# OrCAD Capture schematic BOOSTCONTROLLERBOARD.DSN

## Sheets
1 1 Microcontroller: size C; title: Boost Controller Board - Microcontroller; note: 10021168
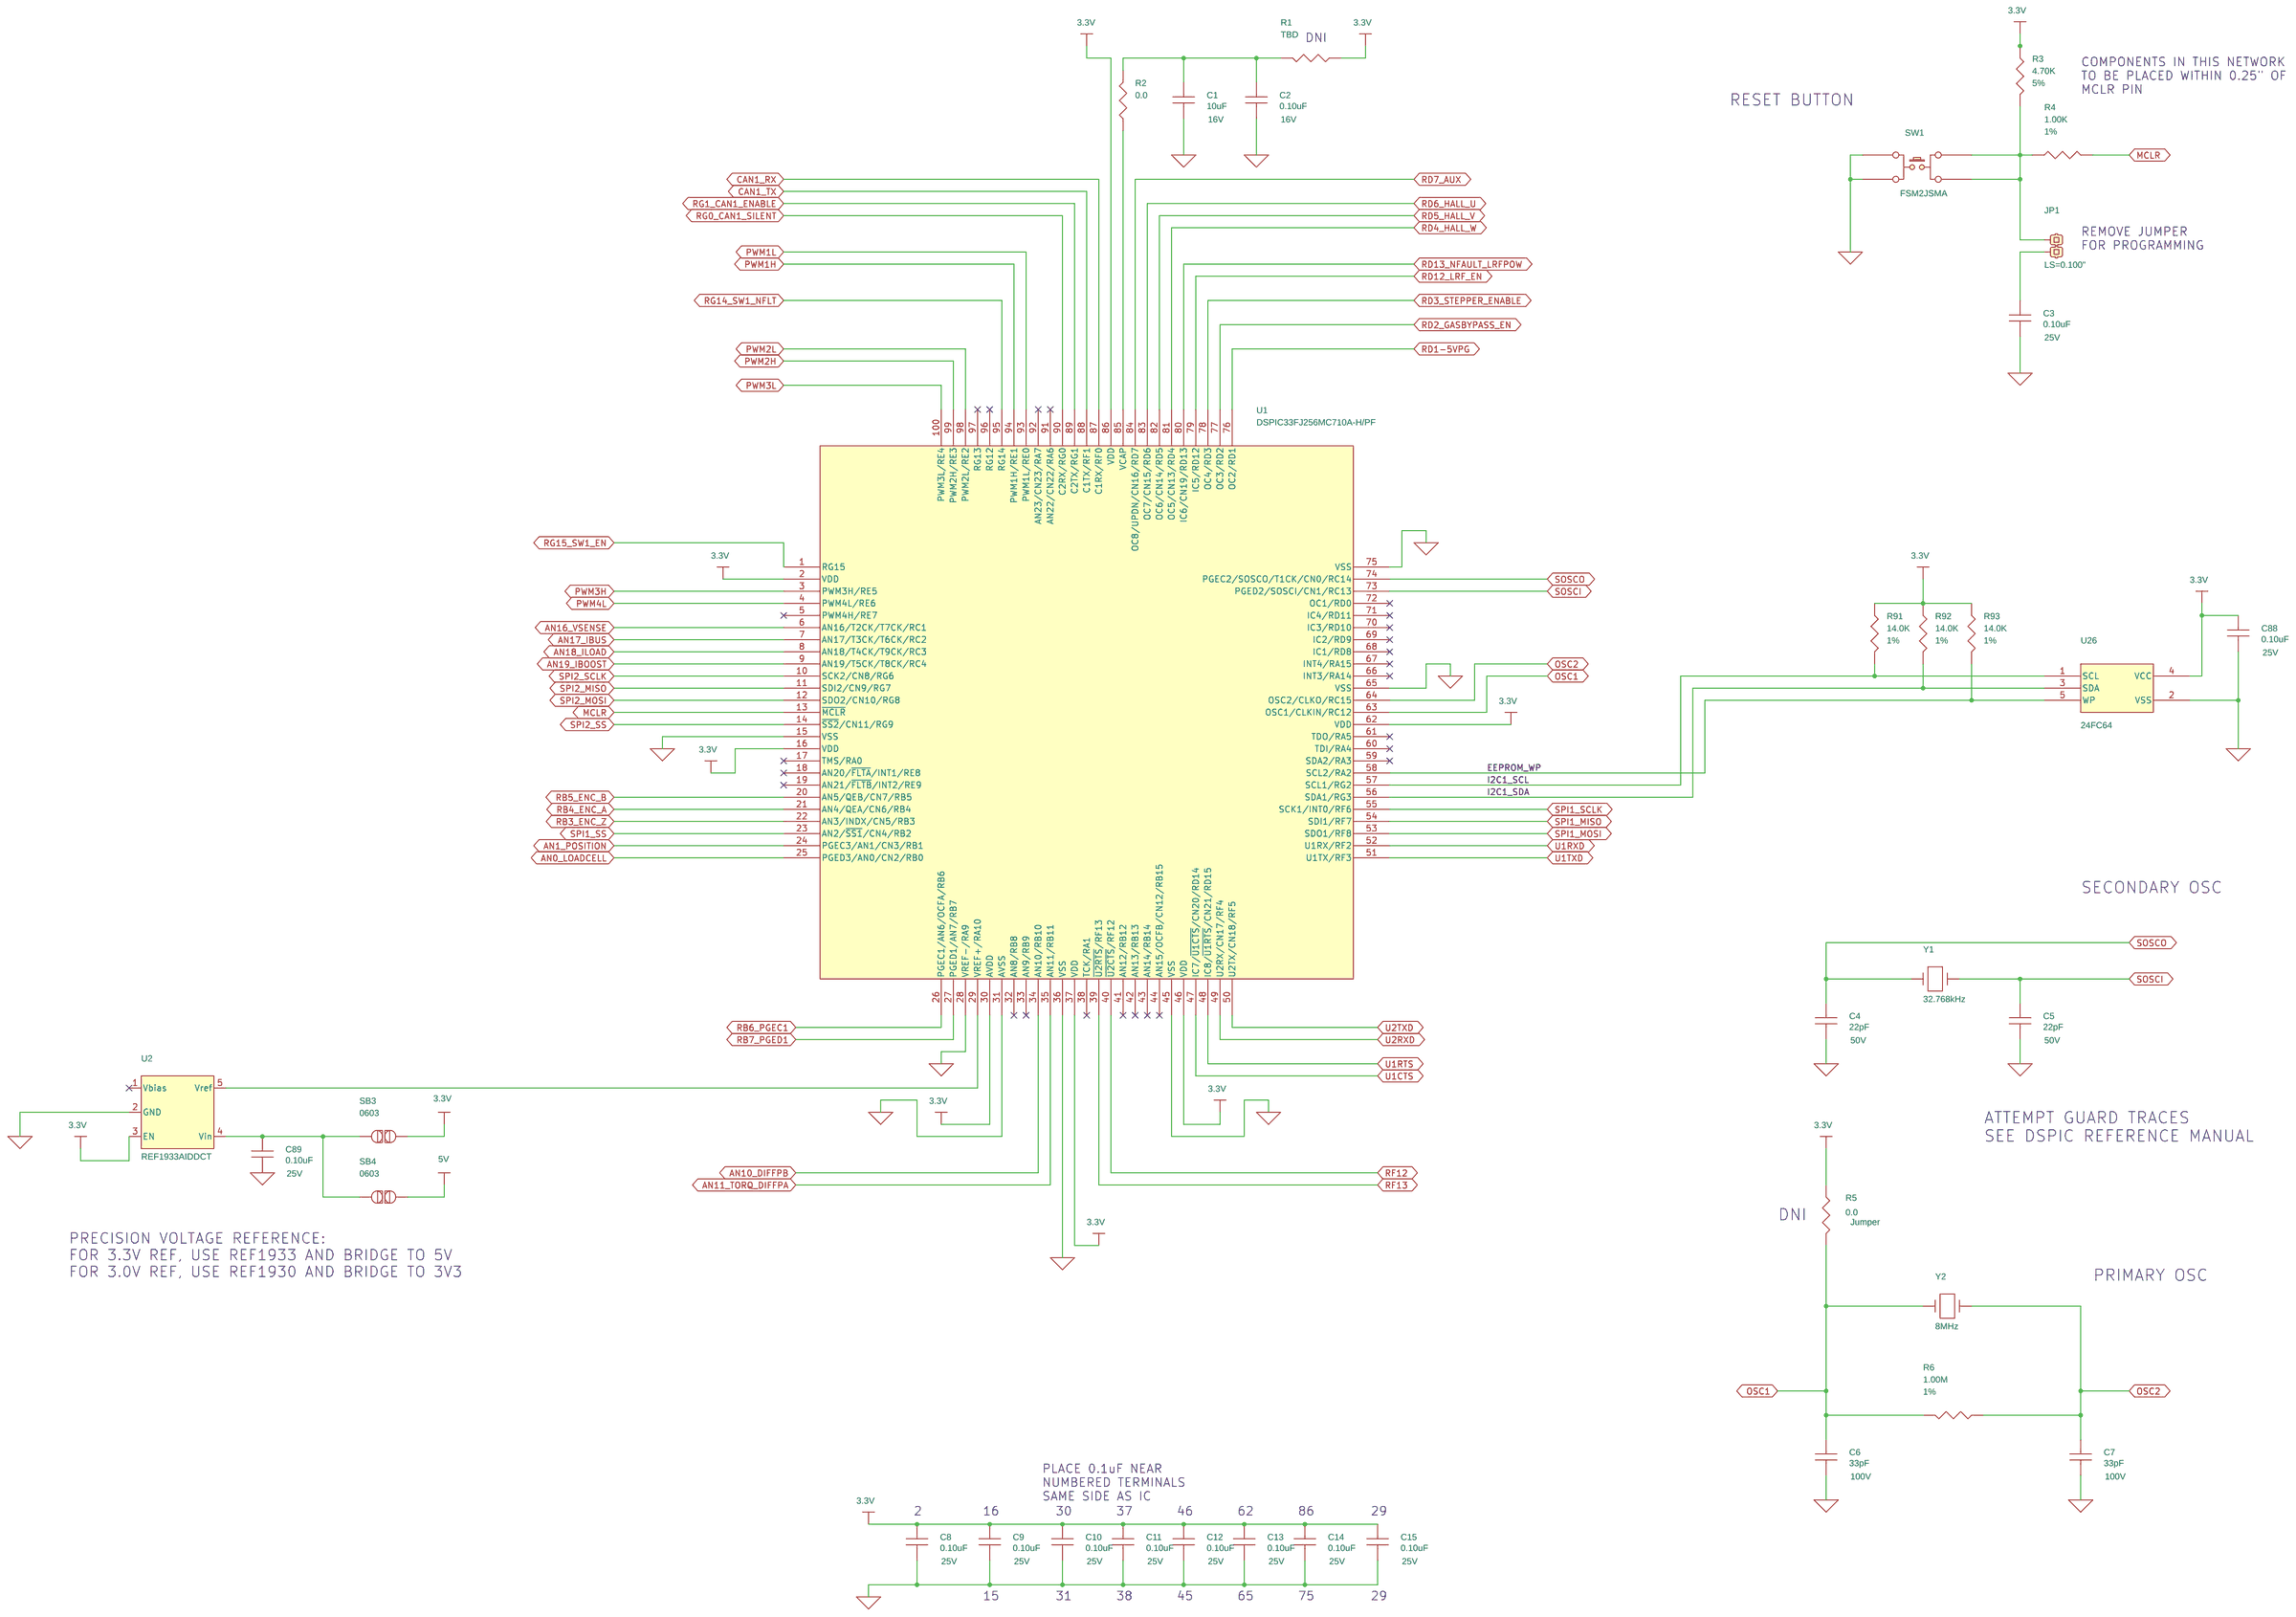
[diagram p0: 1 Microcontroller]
2 2 Power Supply: size C; title: Boost Controller Board - Power Supply
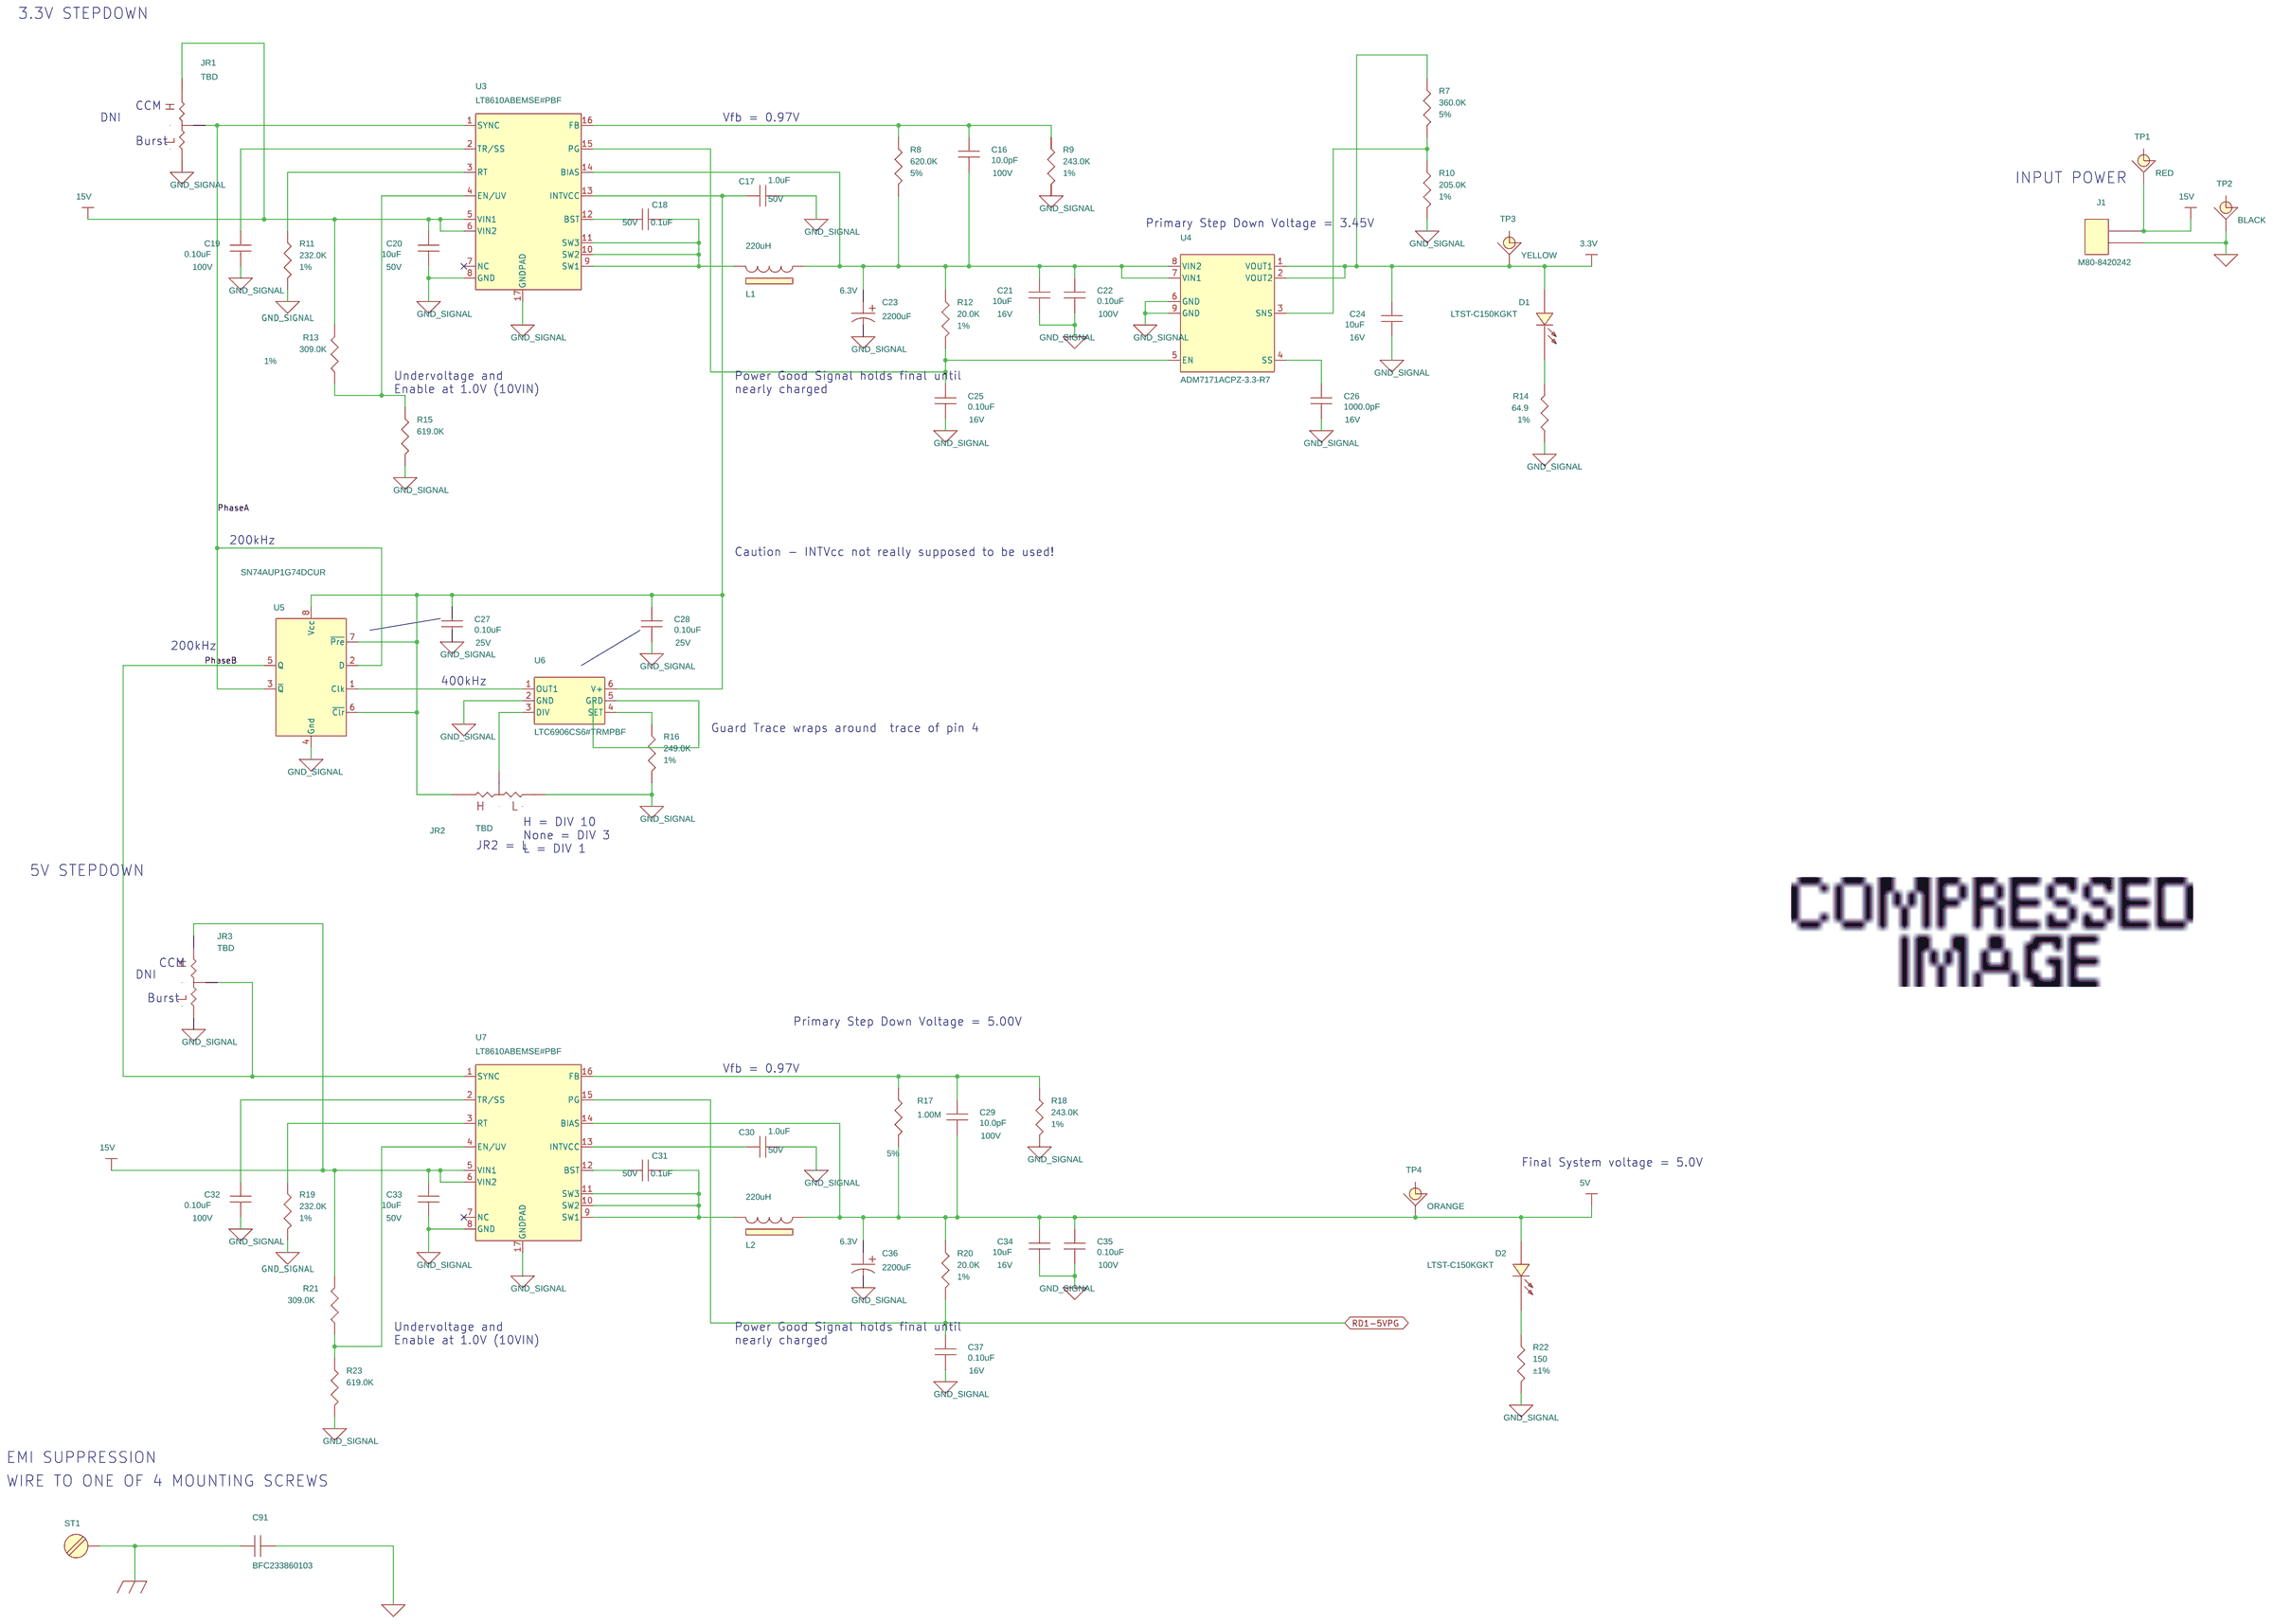
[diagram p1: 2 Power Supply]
3 3 Telemetry: size C; title: Boost Controller Board - Telemetry
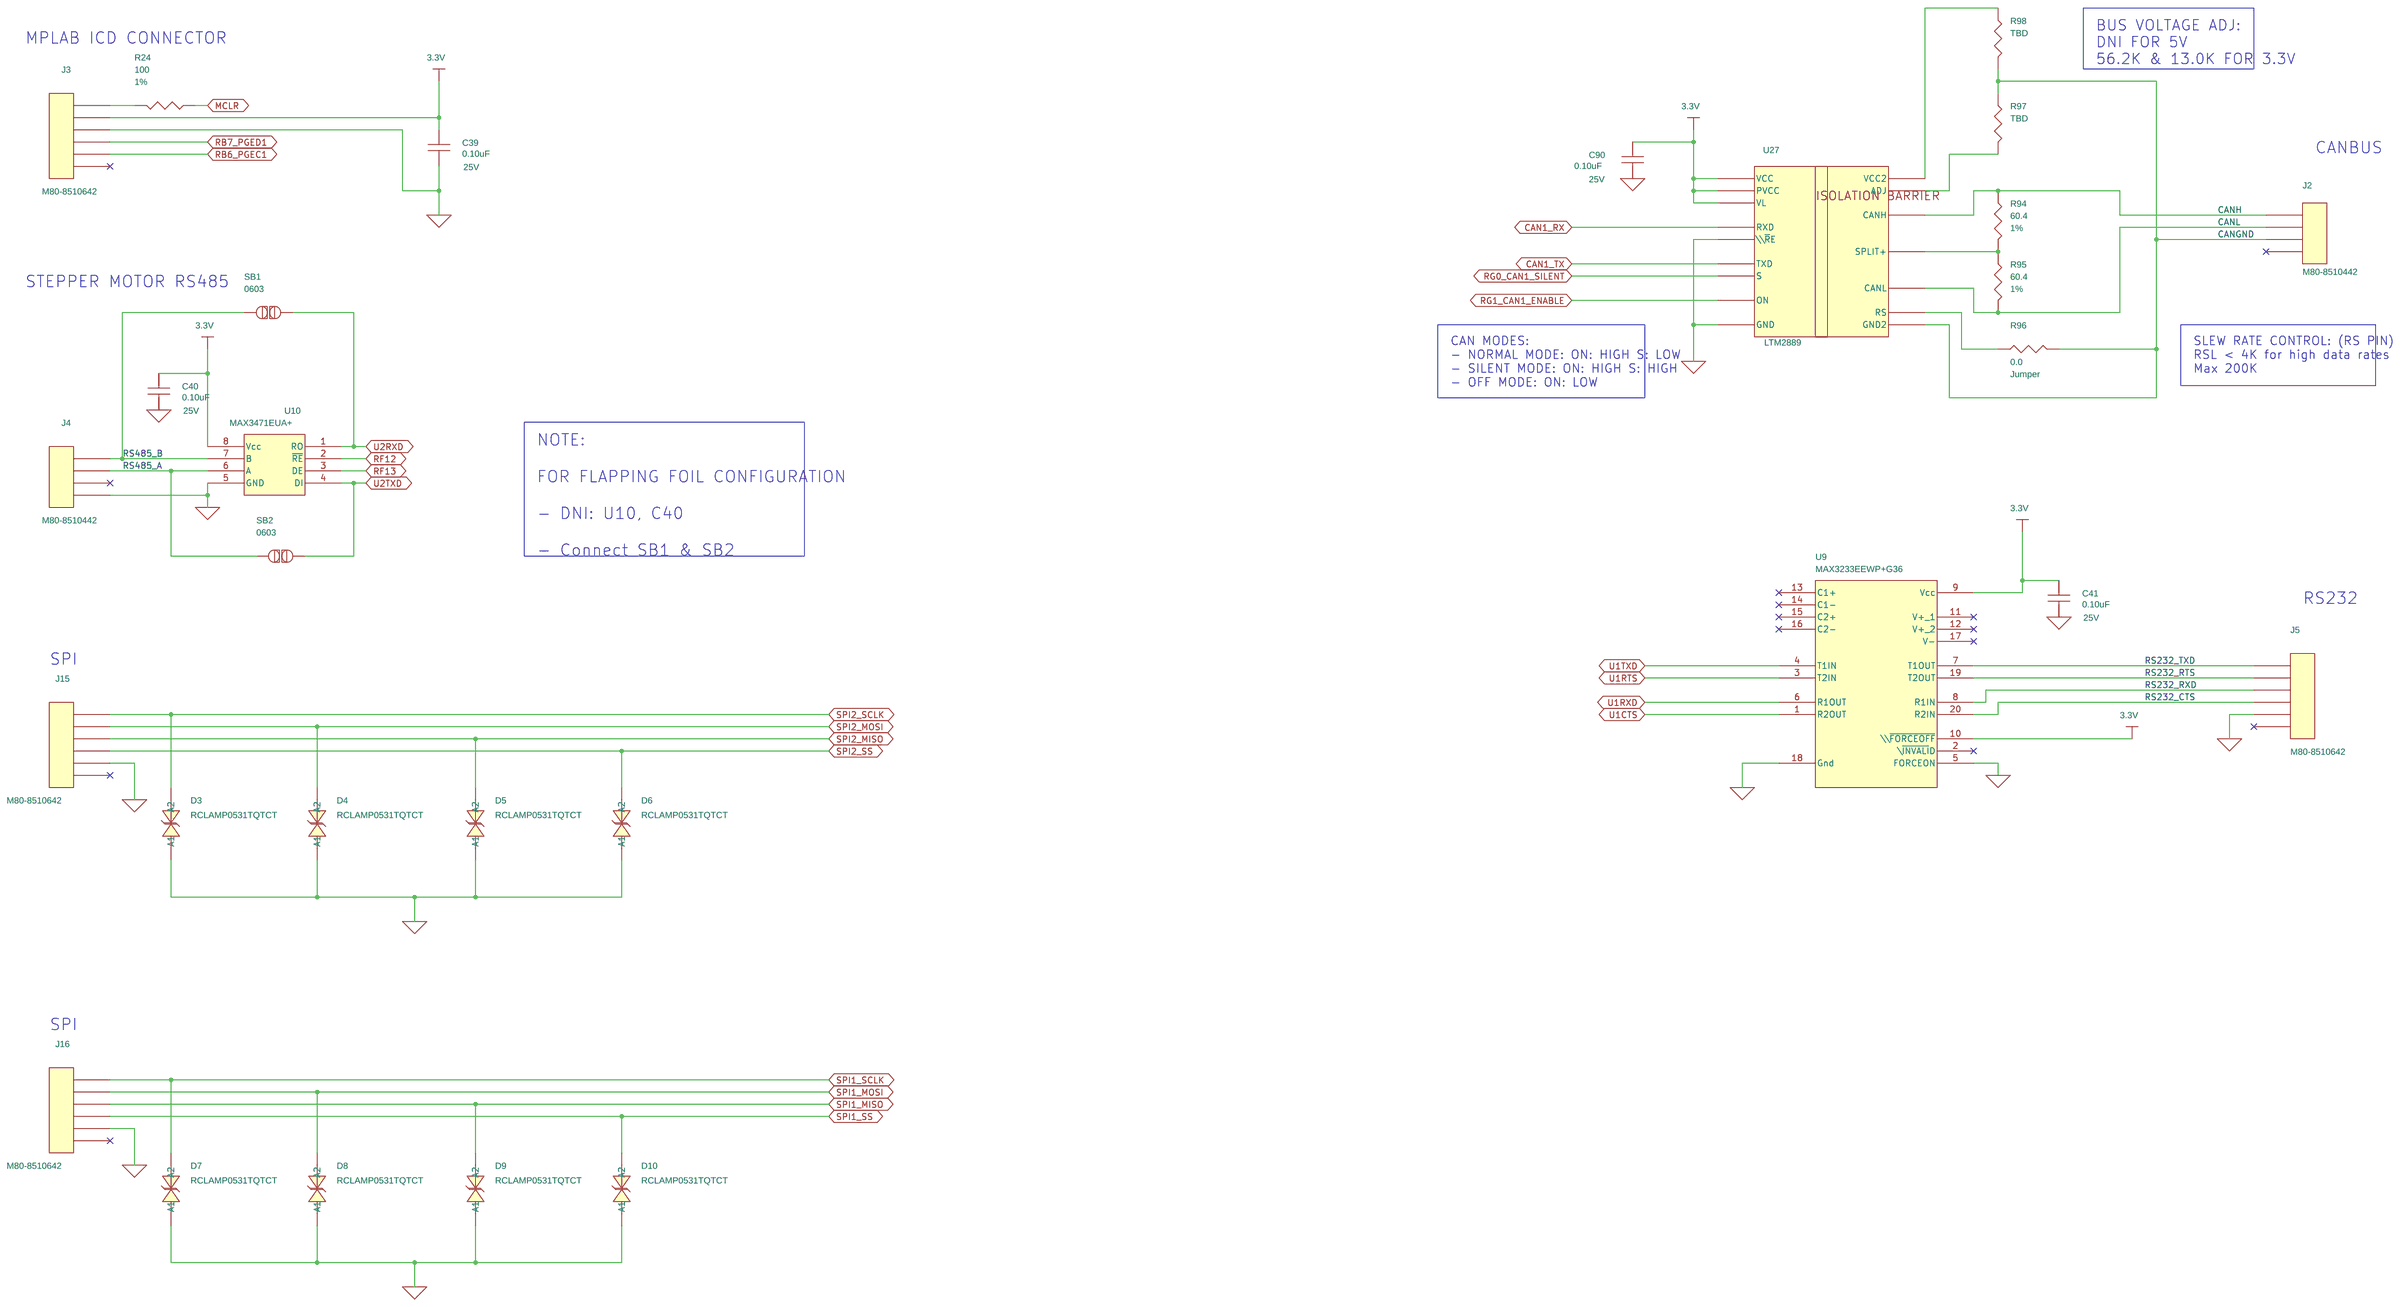
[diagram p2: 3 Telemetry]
4 5 Analog Inputs Sensors: size C; title: Boost Controller Board - Analog Inputs - Sensors
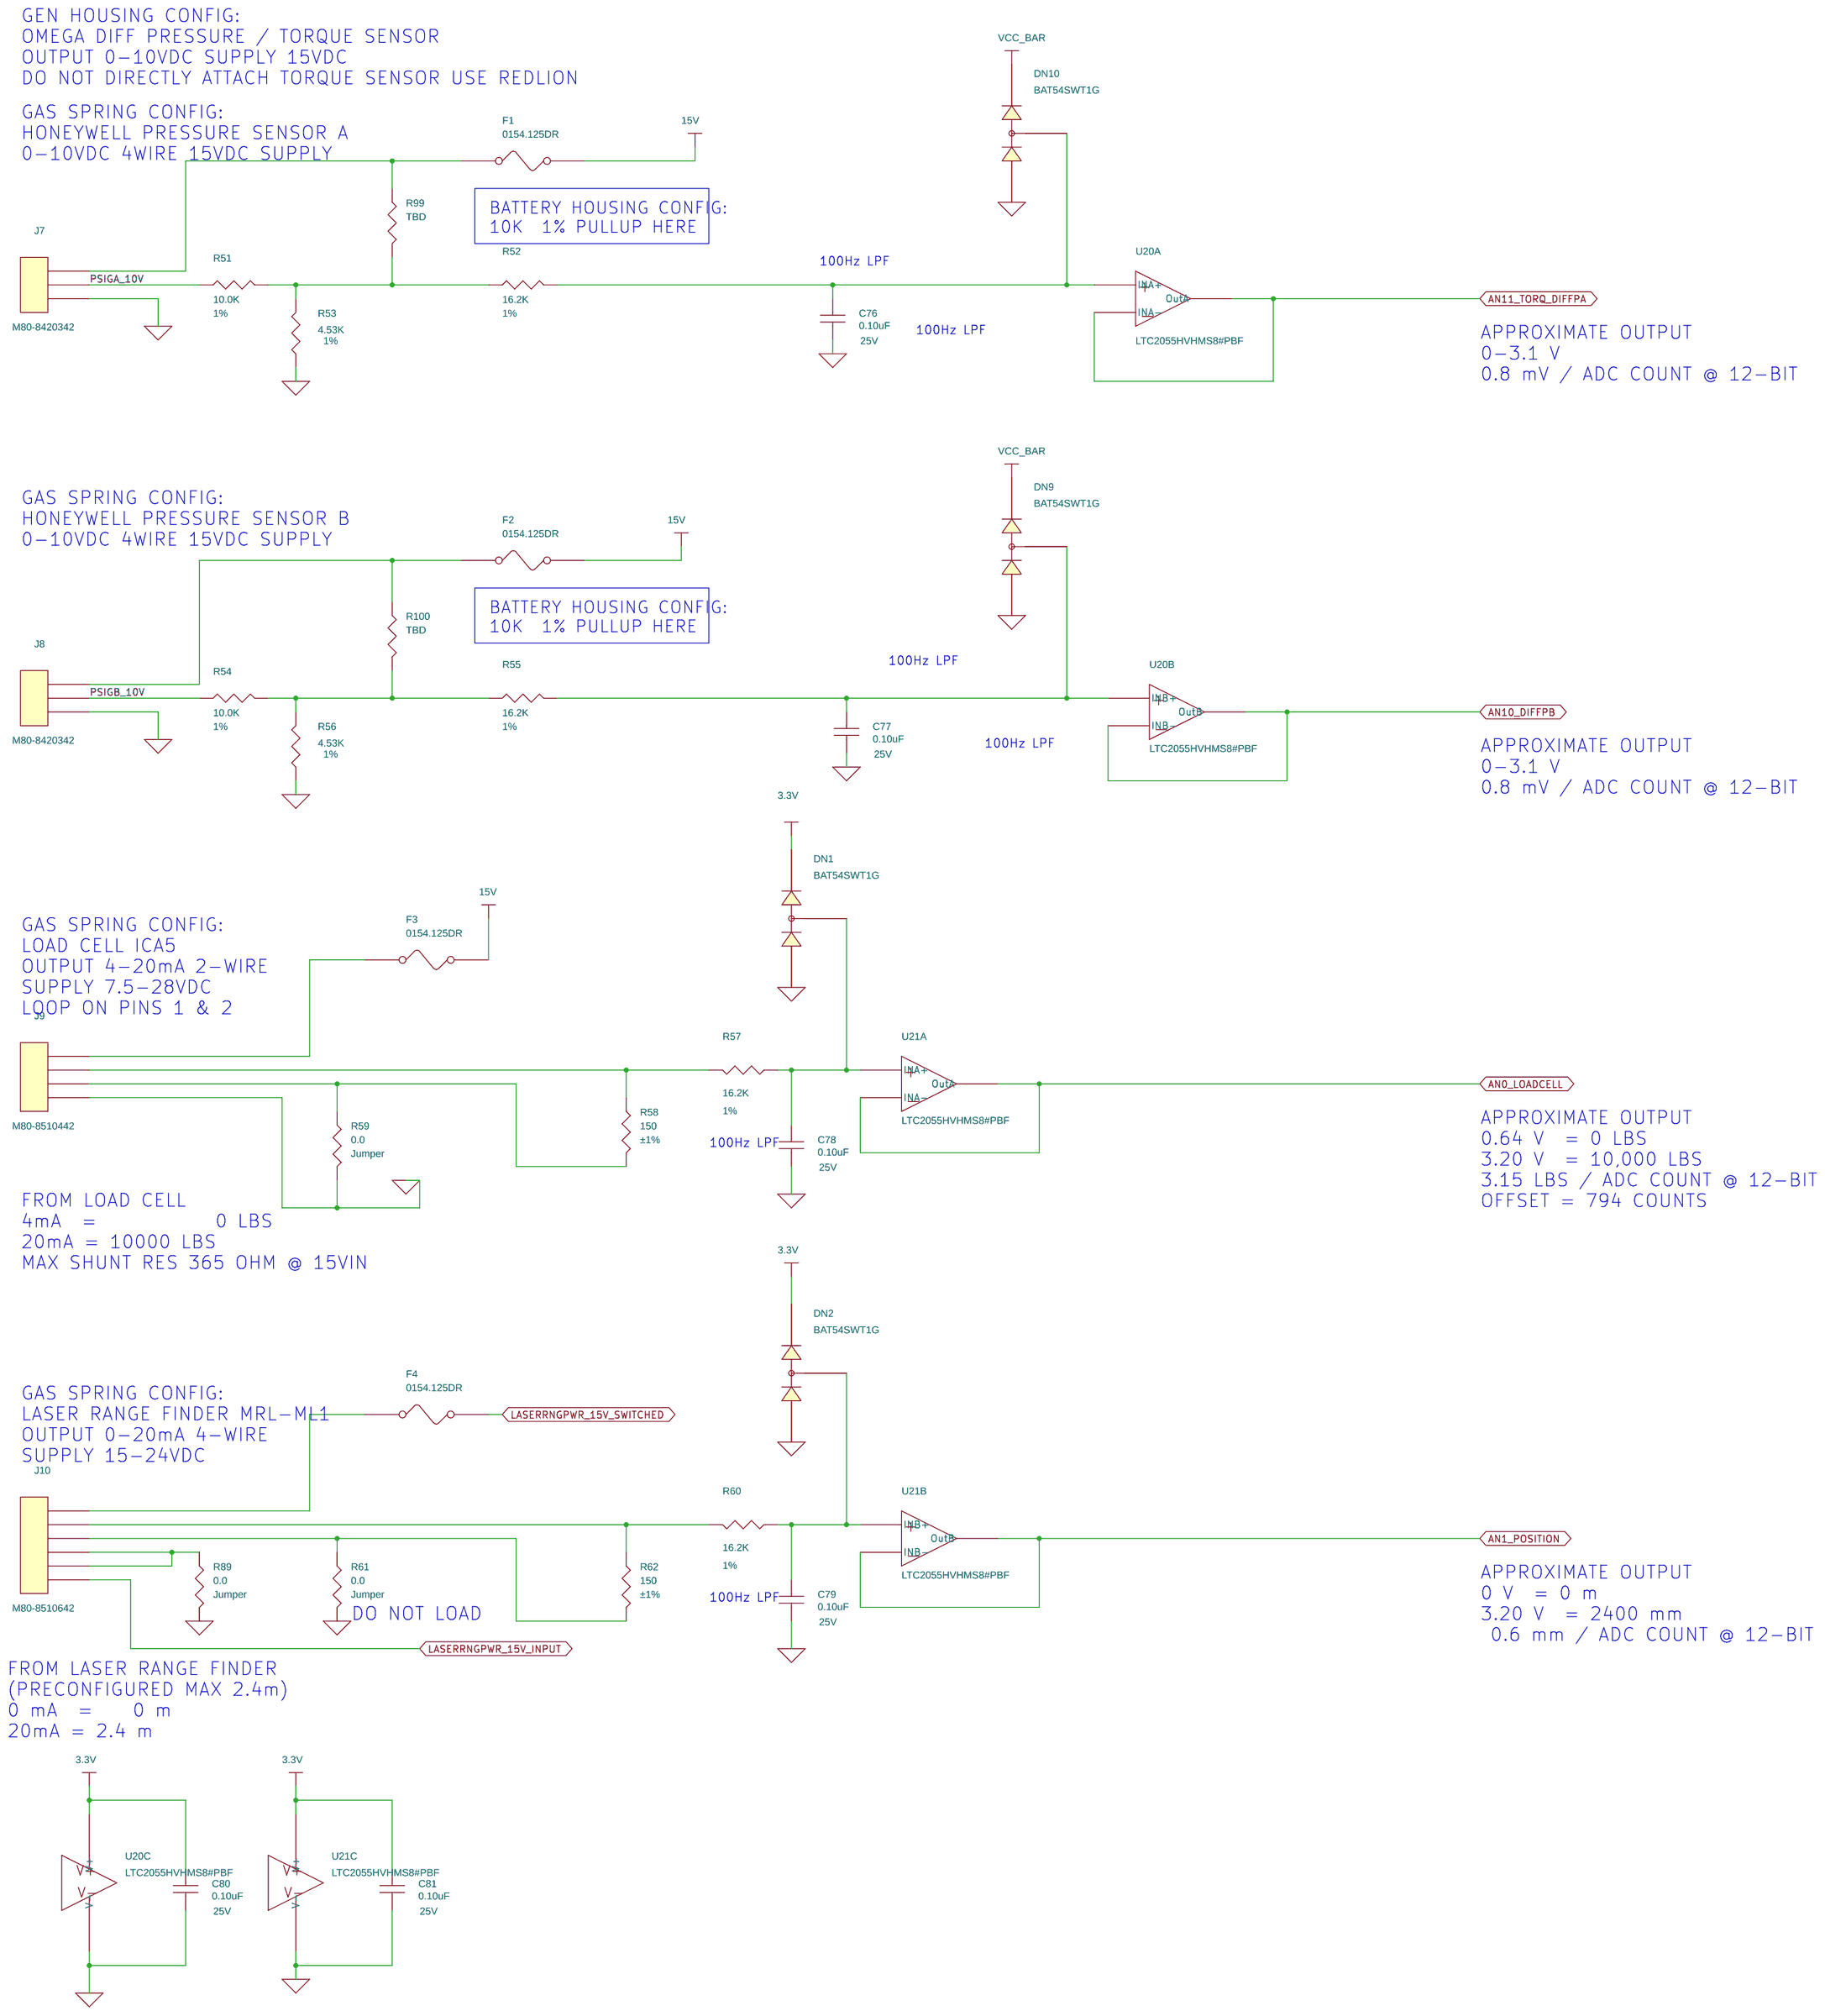
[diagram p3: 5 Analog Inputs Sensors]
5 6 Digital I/O: size C; title: Boost Controller Board - Digital I/O
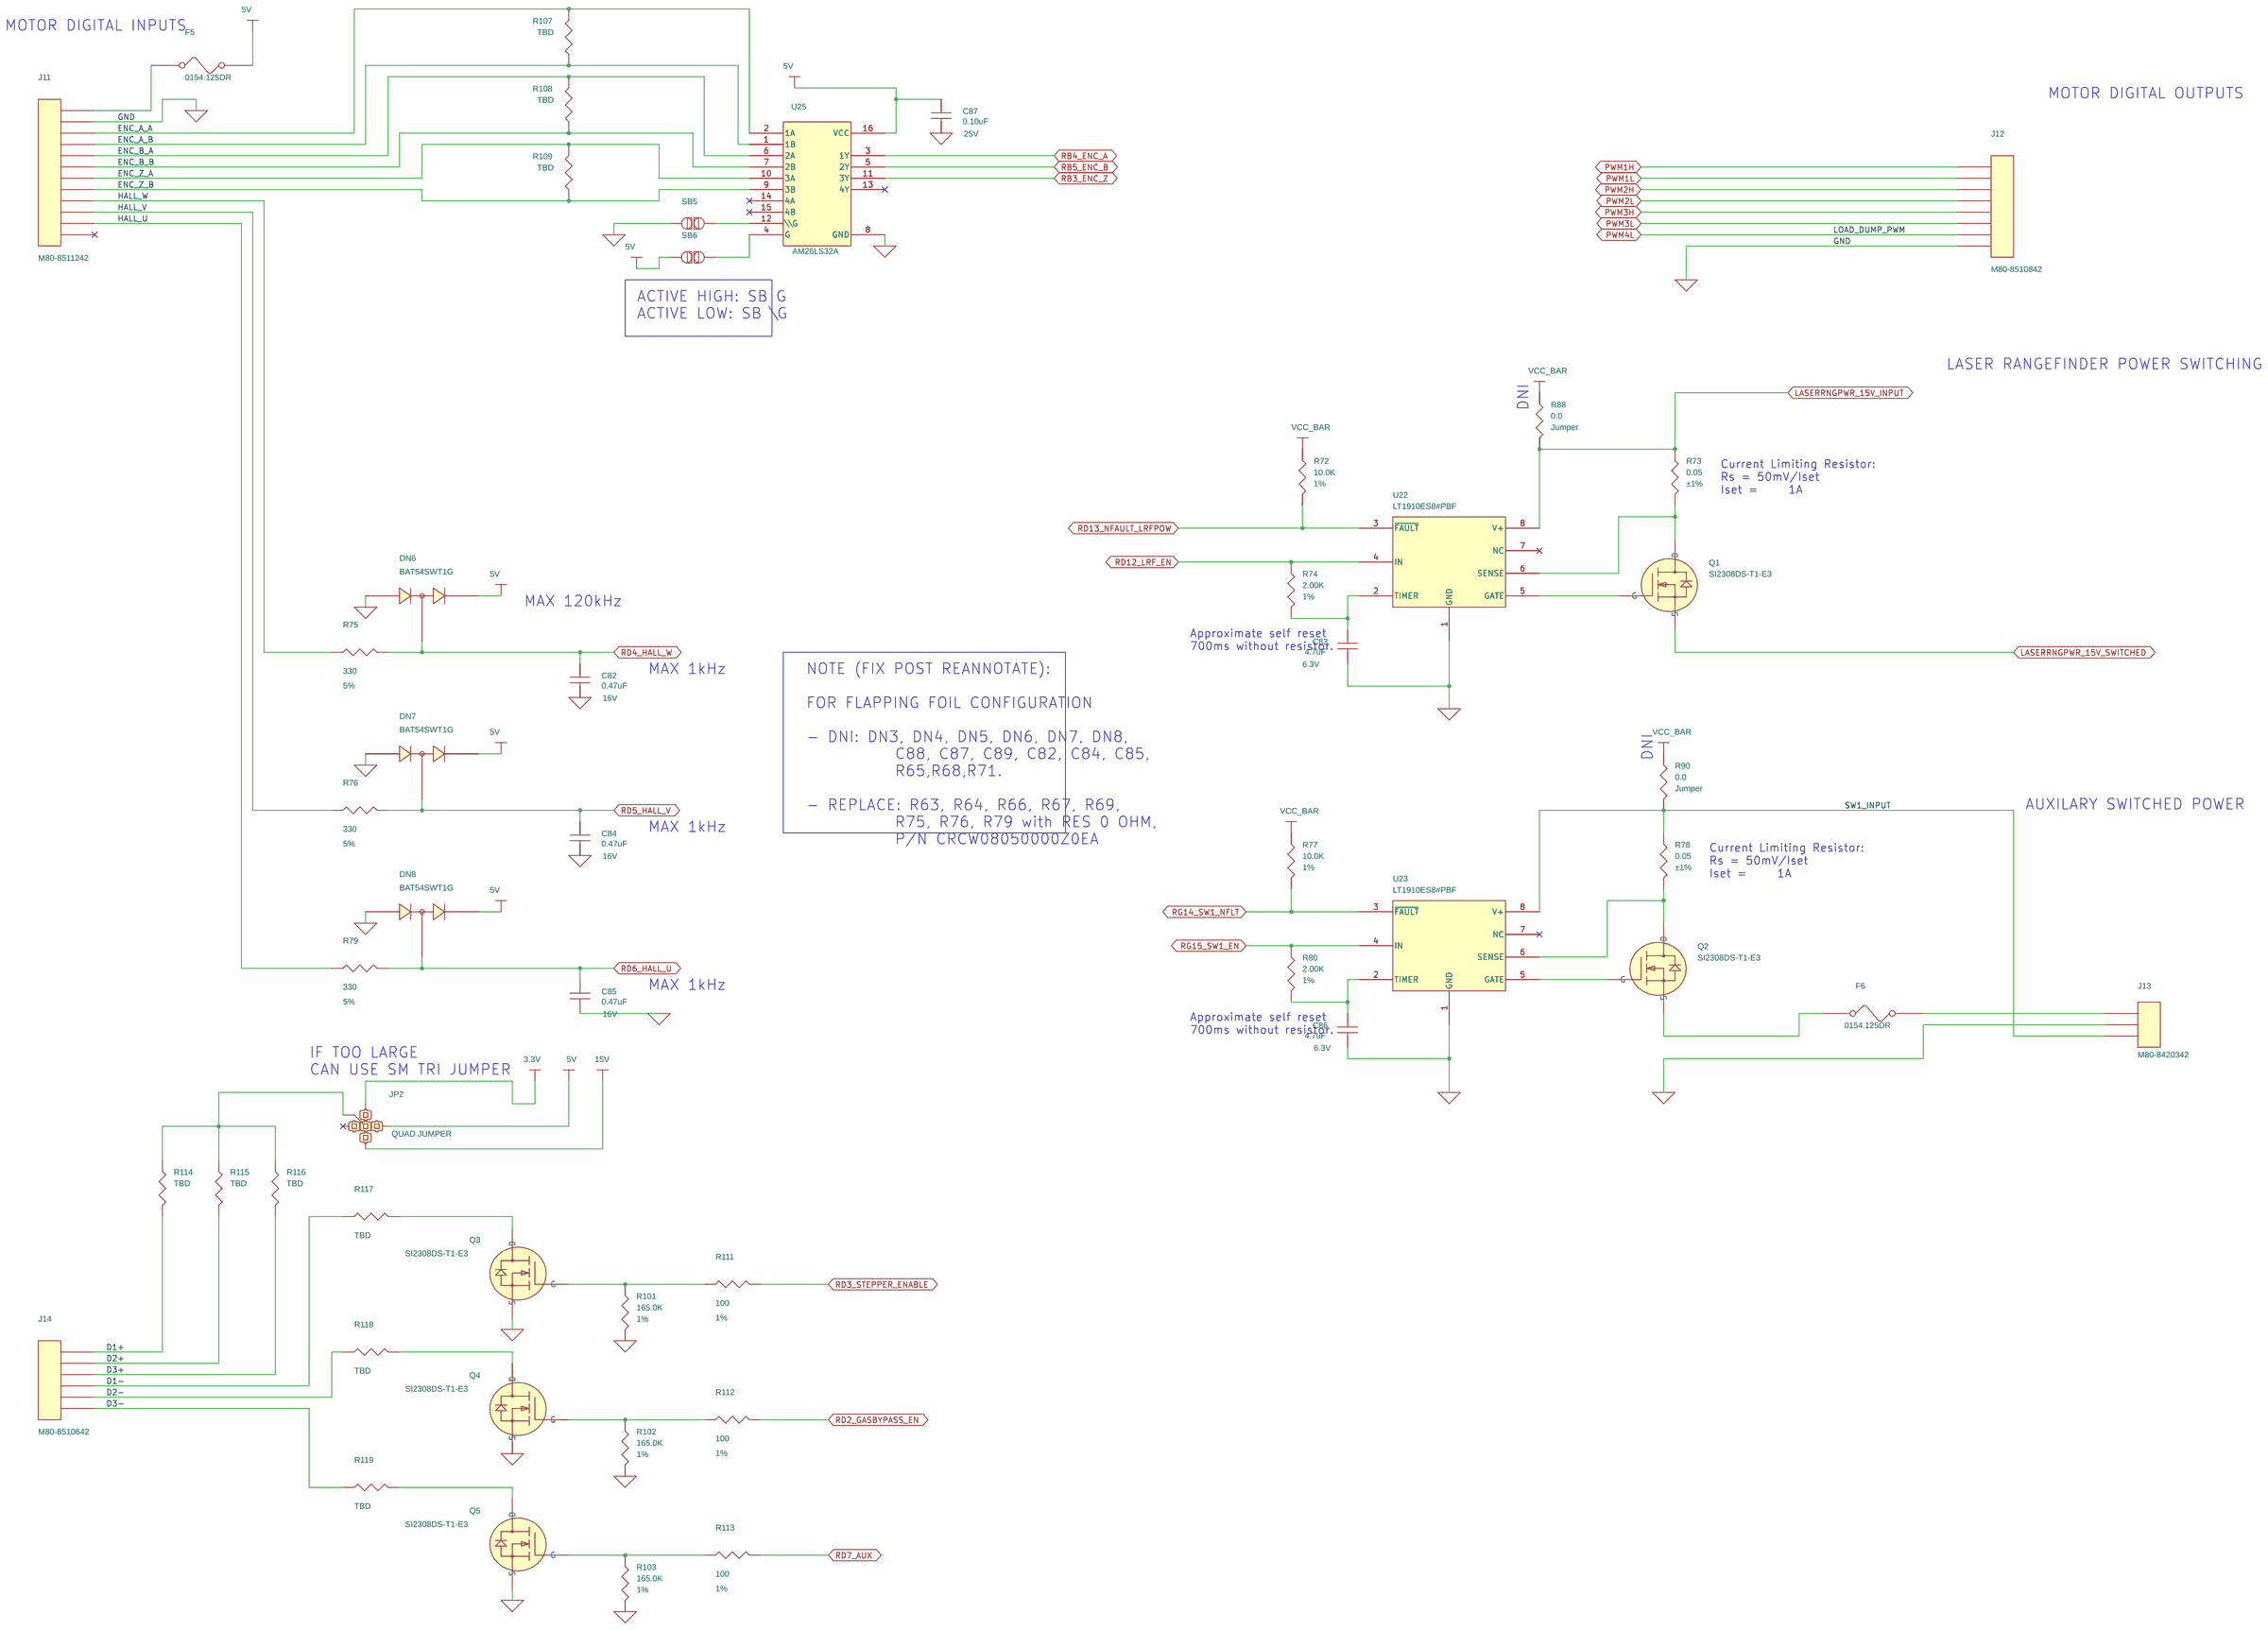
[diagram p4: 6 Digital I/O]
6 4 Analog Inputs V/I Monitors: size C; title: Boost Controller Board - Analog Inputs - Monitors
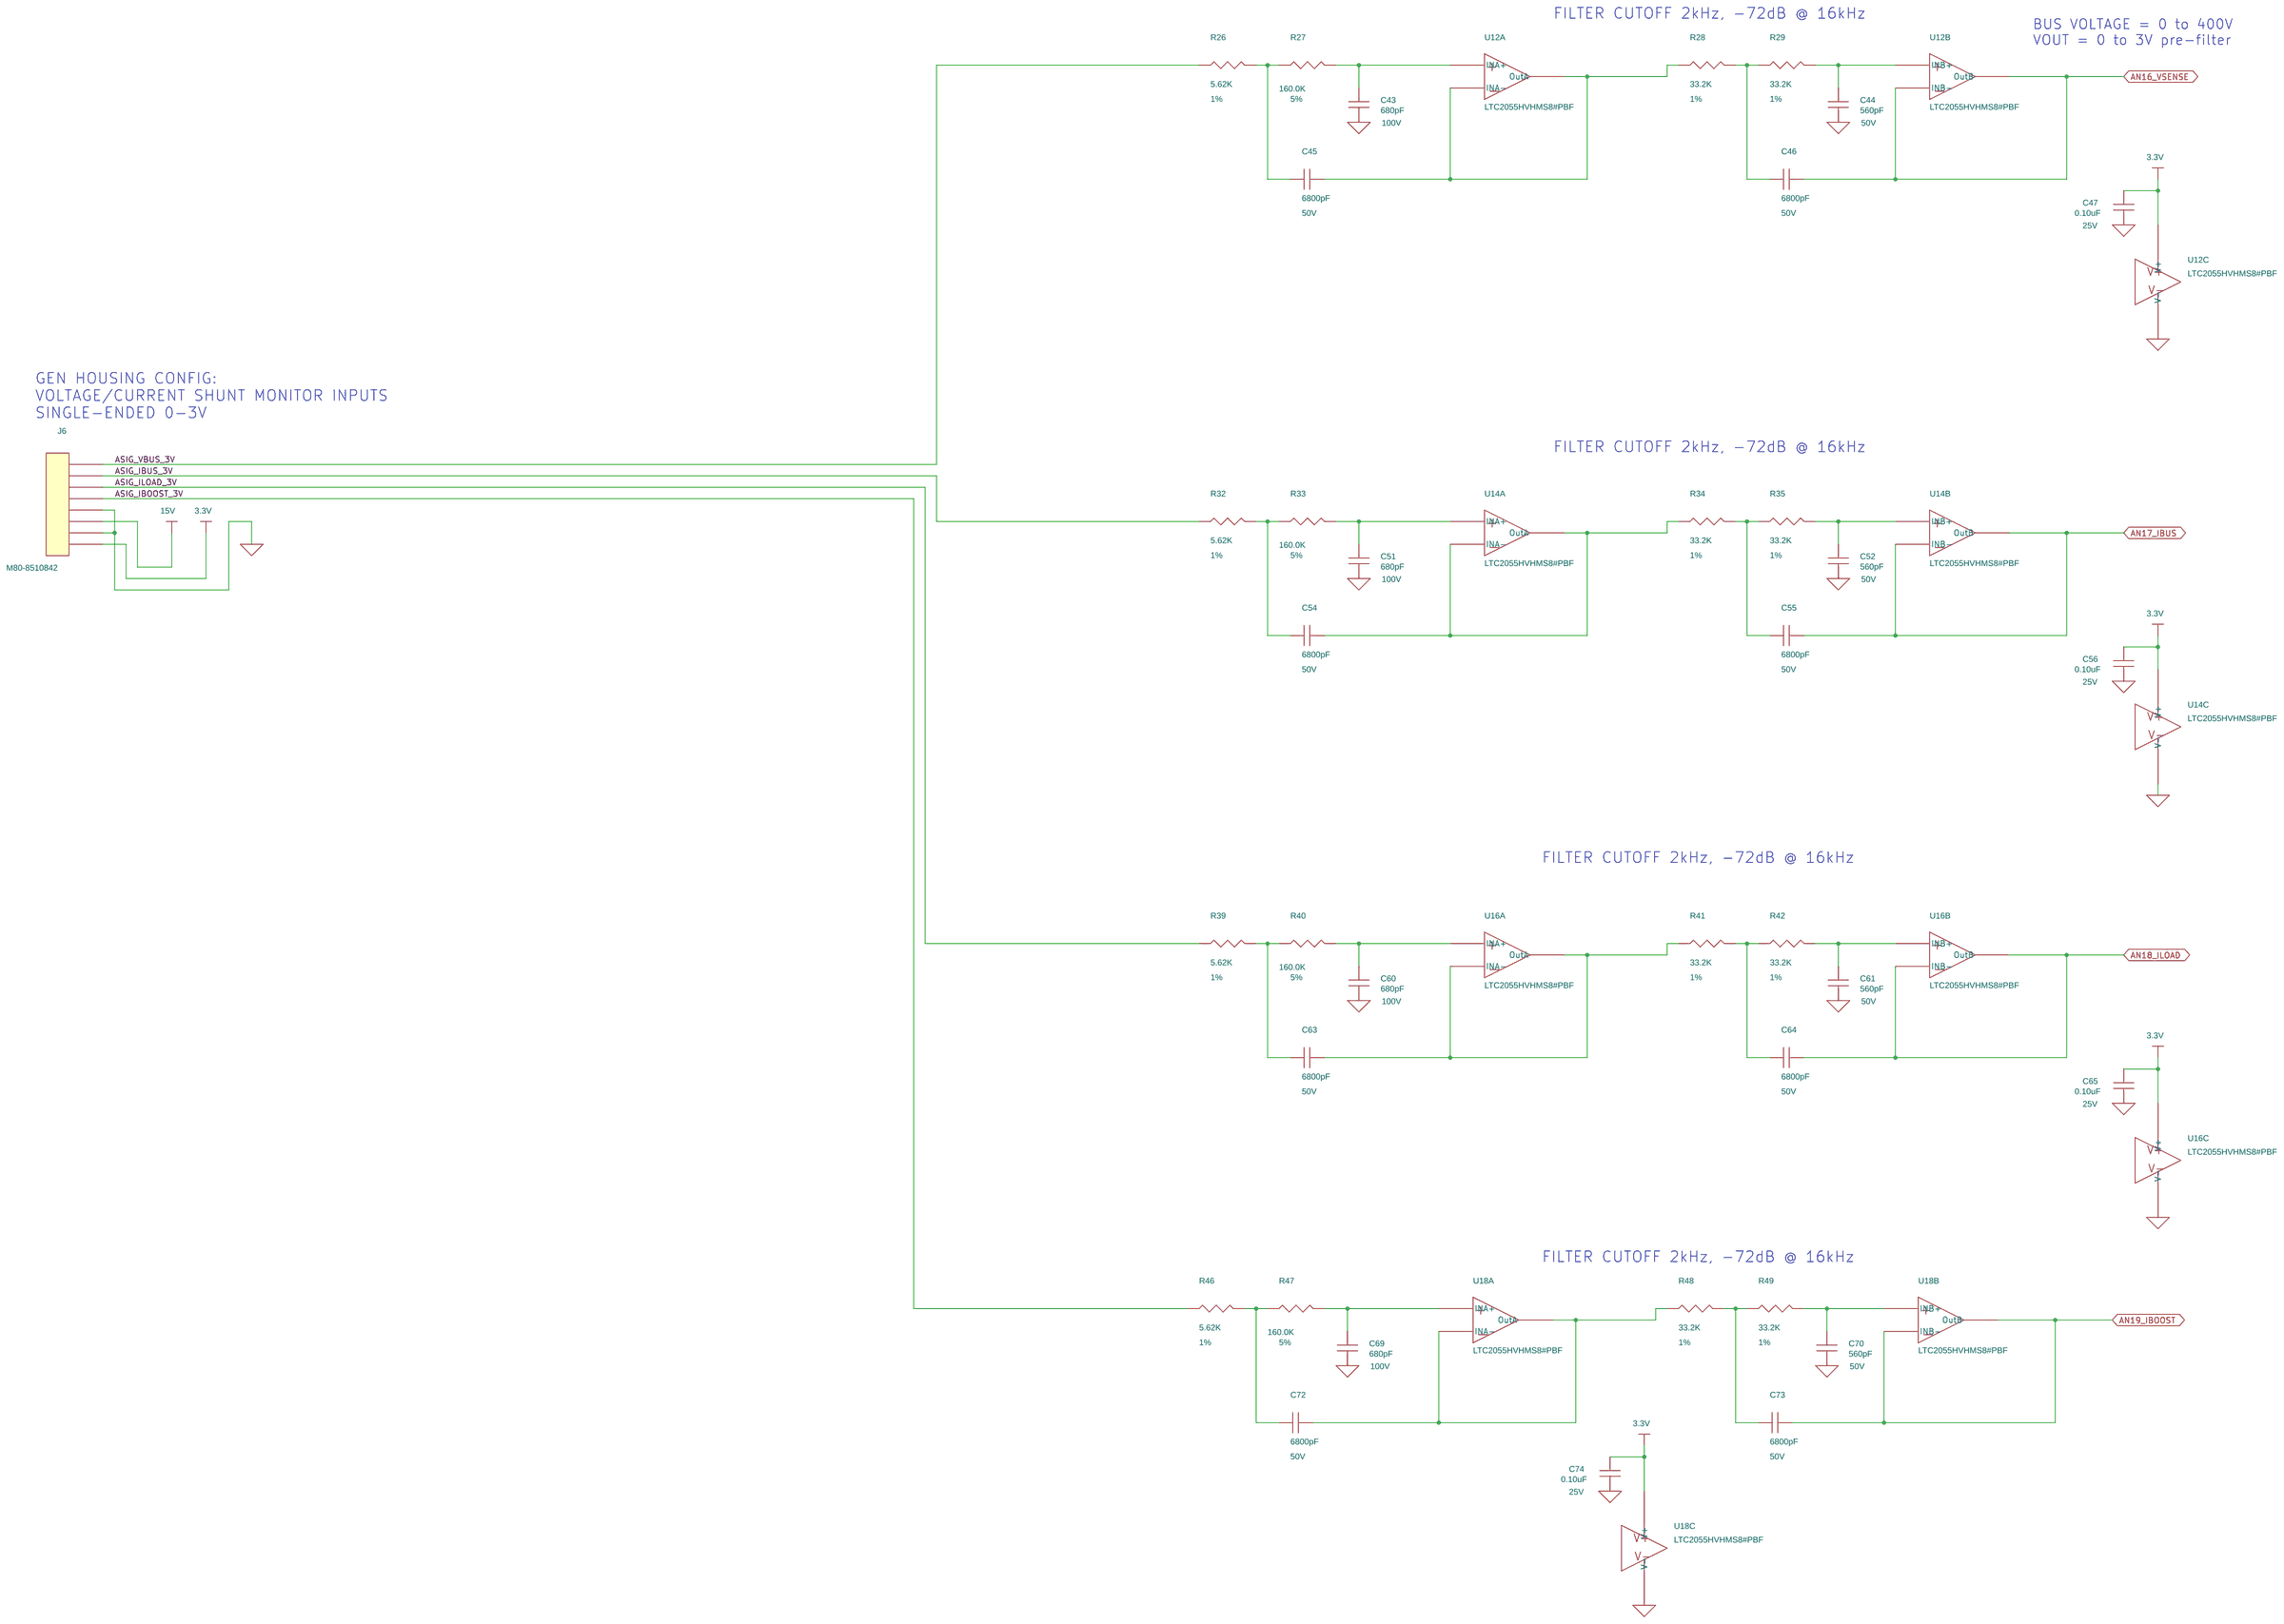
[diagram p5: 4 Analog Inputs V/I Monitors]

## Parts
sheet 1 Microcontroller
C1  10uF  [CAPC2012X135N]
C2  0.10uF  [CAPC1608X87N]
C3  0.10uF  [CAPC1608X87N]
C4  22pF  [CAPC1608X90N_G100]
C5  22pF  [CAPC1608X90N_G100]
C6  33pF  [CAPC1608X90N]
C7  33pF  [CAPC1608X90N]
C8  0.10uF  [CAPC1608X87N]
C9  0.10uF  [CAPC1608X87N]
C10  0.10uF  [CAPC1608X87N]
C11  0.10uF  [CAPC1608X87N]
C12  0.10uF  [CAPC1608X87N]
C13  0.10uF  [CAPC1608X87N]
C14  0.10uF  [CAPC1608X87N]
C15  0.10uF  [CAPC1608X87N]
C88  0.10uF  [CAPC1608X87N]
C89  0.10uF  [CAPC1608X87N]
JP1  LS=0.100"  [HDRV2W64P254_2X1_508X254H1363B]
R1  TBD  [RESC2012X50N]
R2  0.0  [RESC2012X50N]
R3  4.70K  [RESC1608X50N]
R4  1.00K  [RESC1608X50N]
R5  0.0  [RESC1609X55N]
R6  1.00M  [RESC2012X50N]
R91  14.0K  [RESC1608X50N]
R92  14.0K  [RESC1608X50N]
R93  14.0K  [RESC1608X50N]
SB3  0603  [MISC_JUMPER_SM0603]
SB4  0603  [MISC_JUMPER_SM0603]
SW1  FSM2JSMA  [SOIC450P1000X459R-4N]
U1  DSPIC33FJ256MC710A-H/PF  [QFP50P1600X1600X120-100L30N]
U2  REF1933AIDDCT  [SOT95P280X110-5L30N]
U26  24FC64
Y1  32.768kHz  [OSCCC150X320X90-2N]
Y2  8MHz  [XTALSC500X500X135-2N]
sheet 2 Power Supply
C16  10.0pF  [CAPC2012X88N]
C17  1.0uF  [CAPC2012X140N]
C18  0.1uF  [CAPC2013X94N]
C19  0.10uF  [CAPC2012X110N]
C20  10uF  [CAPC5750X250N]
C21  10uF  [CAPC2012X135N]
C22  0.10uF  [CAPC2012X110N]
C23  2200uF  [CAPAE1030X1380DD450L320N]
C24  10uF  [CAPC2012X135N]
C25  0.10uF  [CAPC2012X100N]
C26  1000.0pF  [CAPC2012X88N]
C27  0.10uF  [CAPC1608X87N]
C28  0.10uF  [CAPC1608X87N]
C29  10.0pF  [CAPC2012X88N]
C30  1.0uF  [CAPC2012X140N]
C31  0.1uF  [CAPC2013X94N]
C32  0.10uF  [CAPC2012X110N]
C33  10uF  [CAPC5750X250N]
C34  10uF  [CAPC2012X135N]
C35  0.10uF  [CAPC2012X110N]
C36  2200uF  [CAPAE1030X1380DD450L320N]
C37  0.10uF  [CAPC2012X100N]
C91  BFC233860103  [UNASSIGNED]
D1  LTST-C150KGKT  [LED_LTST-C150xxx]
D2  LTST-C150KGKT  [LED_LTST-C150xxx]
J1  M80-8420242  [HARWIN_M80-8420242]
JR1  TBD  [MISC_0805-3P-JMPR]
JR2  TBD  [MISC_0805-3P-JMPR]
JR3  TBD  [MISC_0805-3P-JMPR]
L1  220uH  [IND_NS-12]
L2  220uH  [IND_NS-12]
R7  360.0K  [RESC1608X50N]
R8  620.0K  [RESC2012X50N]
R9  243.0K  [RESC2012X50N]
R10  205.0K  [RESC1608X50N]
R11  232.0K  [RESC2012X50N]
R12  20.0K  [RESC2012X50N]
R13  309.0K  [RESC2012X50N]
R14  64.9  [RESC1608X50N]
R15  619.0K  [RESC2012X50N]
R16  249.0K  [RESC2012X50N]
R17  1.00M  [RESC1608X50N]
R18  243.0K  [RESC1608X50N]
R19  232.0K  [RESC2012X50N]
R20  20.0K  [RESC2012X50N]
R21  309.0K  [RESC2012X50N]
R22  150  [RESC1609X55N]
R23  619.0K  [RESC2012X50N]
ST1  #4 SCREW TERMINAL  [MNT_C220H125]
TP1  RED  [TP_KEYSTONE_5000s_MINI]
TP2  BLACK  [TP_KEYSTONE_5000s_MINI]
TP3  YELLOW  [TP_KEYSTONE_5000s_MINI]
TP4  ORANGE  [TP_KEYSTONE_5000s_MINI]
U3  LT8610ABEMSE#PBF  [SOP50P490X110-17L30T175X364N]
U4  ADM7171ACPZ-3.3-R7  [SON50P300X300X80-9T170X254N]
U5  SN74AUP1G74DCUR  [SOP50P310X90-8N]
U6  LTC6906CS6#TRMPBF  [SOT95P280X100-6L20N]
U7  LT8610ABEMSE#PBF  [SOP50P490X110-17L30T175X364N]
sheet 3 Telemetry
C39  0.10uF  [CAPC1608X87N]
C40  0.10uF  [CAPC1608X87N]
C41  0.10uF  [CAPC1608X87N]
C90  0.10uF  [CAPC1608X87N]
D3  RCLAMP0531TQTCT  [UNASSIGNED]
D4  RCLAMP0531TQTCT  [UNASSIGNED]
D5  RCLAMP0531TQTCT  [UNASSIGNED]
D6  RCLAMP0531TQTCT  [UNASSIGNED]
D7  RCLAMP0531TQTCT  [UNASSIGNED]
D8  RCLAMP0531TQTCT  [UNASSIGNED]
D9  RCLAMP0531TQTCT  [UNASSIGNED]
D10  RCLAMP0531TQTCT  [UNASSIGNED]
J2  M80-8510442  [HARWIN_M80-8510442]
J3  M80-8510642  [HARWIN_M80-8510642]
J4  M80-8510442  [HARWIN_M80-8510442]
J5  M80-8510642  [HARWIN_M80-8510642]
J15  M80-8510642  [HARWIN_M80-8510642]
J16  M80-8510642  [HARWIN_M80-8510642]
R24  100  [RESC2012X50N]
R94  60.4  [RESC3216X60N]
R95  60.4  [RESC3216X60N]
R96  0.0  [RESC1608X50N]
R97  TBD  [RESC1608X50N]
R98  TBD  [RESC1608X50N]
SB1  0603  [MISC_JUMPER_SM0603]
SB2  0603  [MISC_JUMPER_SM0603]
U9  MAX3233EEWP+G36  [SOIC127P1032X265-20N]
U10  MAX3471EUA+  [SOP65P490X110-8L25N]
U27  LTM2889
sheet 4 Analog Inputs V/I Monitors
C43  680pF  [CAPC2012X88N]
C44  560pF  [CAPC1608X90N]
C45  6800pF  [CAPC2012X90N]
C46  6800pF  [CAPC2012X90N]
C47  0.10uF  [CAPC1608X87N]
C51  680pF  [CAPC2012X88N]
C52  560pF  [CAPC1608X90N]
C54  6800pF  [CAPC2012X90N]
C55  6800pF  [CAPC2012X90N]
C56  0.10uF  [CAPC1608X87N]
C60  680pF  [CAPC2012X88N]
C61  560pF  [CAPC1608X90N]
C63  6800pF  [CAPC2012X90N]
C64  6800pF  [CAPC2012X90N]
C65  0.10uF  [CAPC1608X87N]
C69  680pF  [CAPC2012X88N]
C70  560pF  [CAPC1608X90N]
C72  6800pF  [CAPC2012X90N]
C73  6800pF  [CAPC2012X90N]
C74  0.10uF  [CAPC1608X87N]
J6  M80-8510842  [HARWIN_M80-8510842]
R26  5.62K  [RESC2012X50N]
R27  160.0K  [RESC2012X50N]
R28  33.2K  [RESC2012X50N]
R29  33.2K  [RESC2012X50N]
R32  5.62K  [RESC2012X50N]
R33  160.0K  [RESC2012X50N]
R34  33.2K  [RESC2012X50N]
R35  33.2K  [RESC2012X50N]
R39  5.62K  [RESC2012X50N]
R40  160.0K  [RESC2012X50N]
R41  33.2K  [RESC2012X50N]
R42  33.2K  [RESC2012X50N]
R46  5.62K  [RESC2012X50N]
R47  160.0K  [RESC2012X50N]
R48  33.2K  [RESC2012X50N]
R49  33.2K  [RESC2012X50N]
U12  LTC2055HVHMS8#PBF  [SOP65P490X110-8L30N]  (sections A,B,C)
U14  LTC2055HVHMS8#PBF  [SOP65P490X110-8L30N]  (sections A,B,C)
U16  LTC2055HVHMS8#PBF  [SOP65P490X110-8L30N]  (sections A,B,C)
U18  LTC2055HVHMS8#PBF  [SOP65P490X110-8L30N]  (sections A,B,C)
sheet 5 Analog Inputs Sensors
C76  0.10uF  [CAPC1608X87N]
C77  0.10uF  [CAPC1608X87N]
C78  0.10uF  [CAPC1608X87N]
C79  0.10uF  [CAPC1608X87N]
C80  0.10uF  [CAPC1608X87N]
C81  0.10uF  [CAPC1608X87N]
DN1  BAT54SWT1G  [SOT65P220X100-3N_132]
DN2  BAT54SWT1G  [SOT65P220X100-3N_132]
DN9  BAT54SWT1G  [SOT65P220X100-3N_132]
DN10  BAT54SWT1G  [SOT65P220X100-3N_132]
F1  0154.125DR  [FUSM9750X381N]
F2  0154.125DR  [FUSM9750X381N]
F3  0154.125DR  [FUSM9750X381N]
F4  0154.125DR  [FUSM9750X381N]
J7  M80-8420342  [HARWIN_M80-8420342]
J8  M80-8420342  [HARWIN_M80-8420342]
J9  M80-8510442  [HARWIN_M80-8510442]
J10  M80-8510642  [HARWIN_M80-8510642]
R51  10.0K  [RESC1608X50N]
R52  16.2K  [RESC1608X50N]
R53  4.53K  [RESC1608X50N]
R54  10.0K  [RESC1608X50N]
R55  16.2K  [RESC1608X50N]
R56  4.53K  [RESC1608X50N]
R57  16.2K  [RESC1608X50N]
R58  150  [RESC6332X70N]
R59  0.0  [RESC2012X50N]
R60  16.2K  [RESC1608X50N]
R61  0.0  [RESC2012X50N]
R62  150  [RESC6332X70N]
R89  0.0  [RESC2012X50N]
R99  TBD  [RESC1608X50N]
R100  TBD  [RESC1608X50N]
U20  LTC2055HVHMS8#PBF  [SOP65P490X110-8L30N]  (sections A,B,C)
U21  LTC2055HVHMS8#PBF  [SOP65P490X110-8L30N]  (sections A,B,C)
sheet 6 Digital I/O
C82  0.47uF  [CAPC1608X87N]
C83  4.7uF  [CAPC2012X140N]
C84  0.47uF  [CAPC1608X87N]
C85  0.47uF  [CAPC1608X87N]
C86  4.7uF  [CAPC2012X140N]
C87  0.10uF  [CAPC1608X87N]
DN6  BAT54SWT1G  [SOT65P220X100-3N_132]
DN7  BAT54SWT1G  [SOT65P220X100-3N_132]
DN8  BAT54SWT1G  [SOT65P220X100-3N_132]
F5  0154.125DR  [FUSM9750X381N]
F6  0154.125DR  [FUSM9750X381N]
J11  M80-8511242  [HARWIN_M80-8511242]
J12  M80-8510842  [HARWIN_M80-8510842]
J13  M80-8420342  [HARWIN_M80-8420342]
J14  M80-8510642  [HARWIN_M80-8510642]
JP2  QUAD JUMPER  [MISC_JMPR-SELECT-QUAD]
Q1  SI2308DS-T1-E3  [SOT95P237X112-3N_132]
Q2  SI2308DS-T1-E3  [SOT95P237X112-3N_132]
Q3  SI2308DS-T1-E3  [SOT95P237X112-3N_132]
Q4  SI2308DS-T1-E3  [SOT95P237X112-3N_132]
Q5  SI2308DS-T1-E3  [SOT95P237X112-3N_132]
R72  10.0K  [RESC1608X50N]
R73  0.05  [RESC3116X65N]
R74  2.00K  [RESC1608X50N]
R75  330  [RESC1608X50N]
R76  330  [RESC1608X50N]
R77  10.0K  [RESC1608X50N]
R78  0.05  [RESC3116X65N]
R79  330  [RESC1608X50N]
R80  2.00K  [RESC1608X50N]
R88  0.0  [RESC2012X50N]
R90  0.0  [RESC2012X50N]
R101  165.0K  [RESC1608X50N]
R102  165.0K  [RESC1608X50N]
R103  165.0K  [RESC1608X50N]
R107  TBD  [RESC3216X60N]
R108  TBD  [RESC3216X60N]
R109  TBD  [RESC3216X60N]
R111  100  [RESC1608X50N]
R112  100  [RESC1608X50N]
R113  100  [RESC1608X50N]
R114  TBD  [RESC2012X50N]
R115  TBD  [RESC2012X50N]
R116  TBD  [RESC2012X50N]
R117  TBD  [RESC2012X50N]
R118  TBD  [RESC2012X50N]
R119  TBD  [RESC2012X50N]
SB5  0603  [MISC_JUMPER_SM0603]
SB6  0603  [MISC_JUMPER_SM0603]
U22  LT1910ES8#PBF  [SOIC127P599X175-8L86N]
U23  LT1910ES8#PBF  [SOIC127P599X175-8L86N]
U25  AM26LS32A

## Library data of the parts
C1 C21 C24 C34 = CAP: CAP CER 10UF 16V 20% X7R 0805; CLASS: DISCRETE; Dielectric Type: Capacitors; Manufacturer: Taiyo Yuden; Manufacturer PN: EMK212BB7106MG-T; PART_NUMBER: EMK212BB7106MG-T; Package Size: 0805 (2012 Metric); Rated Voltage: 16V; Temperature Coefficient: X7R; Tolerance: ±20%
C2 = CAP: CAP, CER, 0.10uF, 16V, 10%, X7R, 0603; CLASS: DISCRETE; Dielectric Type: Ceramic; Manufacturer: Kemet; Manufacturer PN: C0603C104K4RAC; PART_NUMBER: C0603C104K4RAC; Package Size: 0603; Rated Voltage: 16V; Temperature Coefficient: X7R; Tolerance: 10%
C3 C8-C15 C27 C28 C39-C41 C47 C56 C65 C74 C76-C81 C87-C90 = CAP: CAP CER 0.1UF 25V 10% X7R 0603; CLASS: DISCRETE; Dielectric Type: Ceramic; Manufacturer: Kemet; Manufacturer PN: C0603C104K3RACTU; PART_NUMBER: C0603C104K3RAC; Package Size: 0603; Rated Voltage: 25V; Temperature Coefficient: X7R; Tolerance: 10%
C4 C5 = CAP: CAP CER 22PF 50V 5% NP0 0603; CLASS: DISCRETE; Dielectric Type: Capacitors; Manufacturer: Murata Electronics North America; Manufacturer PN: GRM1885C1H220JA01D; PART_NUMBER: GRM1885C1H220JA01D; Package Size: 0603 (1608 Metric); Rated Voltage: 50V; Temperature Coefficient: C0G, NP0; Tolerance: ±5%
C6 C7 = CAP: CAP CER 33PF 100V 1% NP0 0603; CLASS: DISCRETE; Dielectric Type: Capacitors; Manufacturer: AVX Corporation; Manufacturer PN: 06031A330FAT2A; PART_NUMBER: 06031A330FAT2A; Package Size: 0603 (1608 Metric); Rated Voltage: 100V; Temperature Coefficient: C0G, NP0; Tolerance: ±1%
JP1 = JUMPER_2PIN: MISC 2 PIN JUMPER 0.100" PITCH 0.025" SQ; CLASS: IO; PART_NUMBER: MISC_JMPR-TH-2PIN
R1 R114-R119 = RES: TO BE DETERMINED, HEIGHT 0.5mm; CLASS: DISCRETE; PART_NUMBER: TBD_R0805; Package Size: 0805
R2 R59 R61 R88-R90 = RES: RES 0.0 OHM 1/8W JUMP 0805 SMD; CLASS: DISCRETE; Manufacturer: Vishay Dale; Manufacturer PN: CRCW08050000Z0EA; PART_NUMBER: CRCW08050000Z0EA; Package Size: 0805 (2012 Metric); Rated Power: 0.125W, 1/8W; Tolerance: Jumper
R3 = RES: CLASS: DISCRETE; Manufacturer: Vishay; Manufacturer PN: CRCW06034K70JNEA; PART_NUMBER: CRCW06034K70JNEA; Package Size: 0603; Rated Power: 0.1W; Temperature Coefficient: 200ppm/K; Tolerance: 5%
R4 = RES: RES SMD 1K OHM 1% 1/10W 0603; CLASS: DISCRETE; Manufacturer: Vishay; Manufacturer PN: CRCW06031K00FKEA; PART_NUMBER: CRCW06031K00FKEA; Package Size: 0603; Rated Power: 0.1W; Temperature Coefficient: 100ppm/K; Tolerance: 1%
R5 = RES: RES 0.0 OHM 1/10W 0603 SMD; CLASS: DISCRETE; Manufacturer: Panasonic - ECG; Manufacturer PN: ERJ-3GEY0R00V; PART_NUMBER: ERJ-3GEY0R00V; Package Size: 0603 (1608 Metric); Rated Power: 0.1W, 1/10W; Temperature Coefficient: -100/ +600ppm/°C; Tolerance: Jumper
R6 = RES: RES 1.00M OHM 1/8W 1% 0805 SMD; CLASS: DISCRETE; Manufacturer: Vishay Dale; Manufacturer PN: CRCW08051M00FKEA; PART_NUMBER: CRCW08051M00FKEA; Package Size: 0805; Rated Power: 0.125W; Temperature Coefficient: 100ppm/K; Tolerance: 1%
R91-R93 = RES: CLASS: DISCRETE; Manufacturer: Vishay; Manufacturer PN: CRCW060314K0FKEA; PART_NUMBER: CRCW060314K0FKEA; Package Size: 0603; Rated Power: 0.1W; Temperature Coefficient: 100ppm/K; Tolerance: 1%
SB1-SB6 = SB_JUMPER: MISC 2 PIN JUMPER SOLDER BRIDGE 0603; CLASS: IO; PART_NUMBER: MISC_SOLDERBRIDGE_SM0603
SW1 = SW_SPST_12_34: SWITCH TACTILE SPST-NO 0.05A 12V; CLASS: DISCRETE; Manufacturer: TE Connectivity; Package Size: 6.00mm x 6.00mm
U1 = dsPIC33F_100TQFP: IC DSC 16BIT 256KB FLASH 100TQFP; CLASS: IC; Manufacturer: Microchip Technology; PART_NUMBER: DSPIC33FJ256MC710A-H/PF-ND; Package Size: 100-TQFP; Supply Voltage: 3 V - 3.6 V
U2 = REF19xx: IC VREF SERIES 3.3V SOT5; CLASS: IC; Manufacturer: Texas Instruments; Package Size: SOT-23-5 Thin, TSOT-23-5
U26 = 24AA_FC_LC_FC64-5
Y1 = CRYSTAL: CRYSTAL 32.7680KHZ 12.5PF SMD; CLASS: DISCRETE; Frequency Tolerance: ±20ppm; Manufacturer: Epson Toyocom Corporation; Manufacturer PN: FC-135 32.7680KA-A3; PART_NUMBER: FC-135 32.7680KA-A3; Package Size: 2-SMD
Y2 = CRYSTAL: CRYSTAL 8.0000MHZ 18PF SMD; CLASS: DISCRETE; Frequency Stability: 30ppm; Frequency Tolerance: 30ppm; Manufacturer: TXC CORPORATION; Manufacturer PN: 7A-8.000MAAJ-T; PART_NUMBER: 7A-8.000MAAJ-T; Package Size: 0.197" L x 0.126" W (5.00mm x 3.20mm)
C16 C29 = CAP: CLASS: DISCRETE; Dielectric Type: Ceramic; Manufacturer: Kemet; Manufacturer PN: C0805C100J1GAC; PART_NUMBER: C0805C100J1GAC; Package Size: 0805; Rated Voltage: 100V; Temperature Coefficient: C0G(NP0); Tolerance: 5%
C17 C30 = CAP: CAP CER 1UF 50V 10% X7R 0805; CLASS: DISCRETE; Dielectric Type: Capacitors; Manufacturer: Kemet; Manufacturer PN: C0805C105K5RACTU; PART_NUMBER: C0805C105K5RACTU; Package Size: 0805 (2012 Metric); Rated Voltage: 50V; Temperature Coefficient: X7R; Tolerance: ±10%
C18 C31 = CAP: CAP CER 0.1UF 50V 5% X7R 0805; CLASS: DISCRETE; Dielectric Type: Capacitors; Manufacturer: AVX Corporation; Manufacturer PN: 08055C104JAT2A; PART_NUMBER: 08055C104JAT2A; Package Size: 0805 (2012 Metric); Rated Voltage: 50V; Temperature Coefficient: X7R; Tolerance: ±5%
C19 C22 C32 C35 = CAP: CAP CER 0.1UF 100V 10% X7R 0805; CLASS: DISCRETE; Dielectric Type: Ceramic; Manufacturer: Kemet; Manufacturer PN: C0805C104K1RACTU; PART_NUMBER: C0805C104K1RAC; Package Size: 0805; Rated Voltage: 100V; Temperature Coefficient: X7R; Tolerance: 10%
C20 C33 = CAP: CAP CER 10UF 50V X7R 20% 2220; CLASS: DISCRETE; Dielectric Type: Ceramic; Manufacturer: TDK Corporation; Manufacturer PN: C5750X7R1H106M; PART_NUMBER: C5750X7R1H106M; Package Size: 2220 (5750 Metric); Rated Voltage: 50V; Temperature Coefficient: X7R; Tolerance: ±20%
C23 C36 = CAP_P: CAP ALUM 2200UF 6.3V 20% SMD; CLASS: DISCRETE; Dielectric Type: Capacitors; Manufacturer: Nichicon; Manufacturer PN: UCL0J222MNL1GS; PART_NUMBER: UCL0J222MNL1GS; Package Size: Radial, Can - SMD; Rated Voltage: 6.3V; Tolerance: 20%
C25 C37 = CAP: CLASS: DISCRETE; Dielectric Type: Ceramic; Manufacturer: Kemet; Manufacturer PN: C0805C104K4RAC; PART_NUMBER: C0805C104K4RAC; Package Size: 0805; Rated Voltage: 16V; Temperature Coefficient: X7R; Tolerance: 10%
C26 = CAP: CLASS: DISCRETE; Dielectric Type: Ceramic; Manufacturer: Kemet; Manufacturer PN: C0805C102K4RAC; PART_NUMBER: C0805C102K4RAC; Package Size: 0805; Rated Voltage: 16V; Temperature Coefficient: X7R; Tolerance: 10%
C91 = CAP: CAP FILM 10000PF 20% 1KVDC RAD; CLASS: DISCRETE; Dielectric Type: Polypropylene (PP), Metallized; Manufacturer: Vishay BC Components; PART_NUMBER: TMP-2274; Package Size: Radial; Tolerance: 20%
D1 D2 = LED: LED GREEN CLEAR 1206 SMD; CLASS: DISCRETE; LED Color: Green; Manufacturer: Lite-On Inc; Package Size: 1206 (3216 Metric); Rated Voltage: 2V
J1 = CON2: CONN HDR 2MM R/A W/LATCH 2POS; CLASS: IO; Manufacturer: Harwin Inc
JR1-JR3 = RES_3PIN-JMPR: 0805 3PIN JUMPER; CLASS: DISCRETE; PART_NUMBER: SM_0805-3P-JMPR; Package Size: 0805
L1 L2 = IND_FERRITE: FIXED IND 220UH 1.35A 245 MOHM; CLASS: DISCRETE; Manufacturer: Taiyo Yuden; Manufacturer PN: NS12575T221MN; PART_NUMBER: NS12575T221MN; Package Size: Nonstandard; Tolerance: 20%
R7 = RES: CLASS: DISCRETE; Manufacturer: Vishay; Manufacturer PN: CRCW0603360KJNEA; PART_NUMBER: CRCW0603360KJNEA; Package Size: 0603; Rated Power: 0.1W; Temperature Coefficient: 200ppm/K; Tolerance: 5%
R8 = RES: CLASS: DISCRETE; Manufacturer: Vishay; Manufacturer PN: CRCW0805620KJNEA; PART_NUMBER: CRCW0805620KJNEA; Package Size: 0805; Rated Power: 0.125W; Temperature Coefficient: 200ppm/K; Tolerance: 5%
R9 = RES: CLASS: DISCRETE; Manufacturer: Vishay; Manufacturer PN: CRCW0805243KFKEA; PART_NUMBER: CRCW0805243KFKEA; Package Size: 0805; Rated Power: 0.125W; Temperature Coefficient: 100ppm/K; Tolerance: 1%
R10 = RES: CLASS: DISCRETE; Manufacturer: Vishay; Manufacturer PN: CRCW0603205KFKEA; PART_NUMBER: CRCW0603205KFKEA; Package Size: 0603; Rated Power: 0.1W; Temperature Coefficient: 100ppm/K; Tolerance: 1%
R11 R19 = RES: CLASS: DISCRETE; Manufacturer: Vishay; Manufacturer PN: CRCW0805232KFKEA; PART_NUMBER: CRCW0805232KFKEA; Package Size: 0805; Rated Power: 0.125W; Temperature Coefficient: 100ppm/K; Tolerance: 1%
R12 R20 = RES: CLASS: DISCRETE; Manufacturer: Vishay; Manufacturer PN: CRCW080520K0FKEA; PART_NUMBER: CRCW080520K0FKEA; Package Size: 0805; Rated Power: 0.125W; Temperature Coefficient: 100ppm/K; Tolerance: 1%
R13 R21 = RES: CLASS: DISCRETE; Manufacturer: Vishay; Manufacturer PN: CRCW0805309KFKEA; PART_NUMBER: CRCW0805309KFKEA; Package Size: 0805; Rated Power: 0.125W; Temperature Coefficient: 100ppm/K; Tolerance: 1%
R14 = RES: CLASS: DISCRETE; Manufacturer: Vishay; Manufacturer PN: CRCW060364R9FKEA; PART_NUMBER: CRCW060364R9FKEA; Package Size: 0603; Rated Power: 0.1W; Temperature Coefficient: 100ppm/K; Tolerance: 1%
R15 R23 = RES: CLASS: DISCRETE; Manufacturer: Vishay; Manufacturer PN: CRCW0805619KFKEA; PART_NUMBER: CRCW0805619KFKEA; Package Size: 0805; Rated Power: 0.125W; Temperature Coefficient: 100ppm/K; Tolerance: 1%
R16 = RES: RES 249K OHM 1/8W 1% 0805 SMD; CLASS: DISCRETE; Manufacturer: Vishay Dale; Manufacturer PN: CRCW0805249KFKEA; PART_NUMBER: CRCW0805249KFKEA; Package Size: 0805; Rated Power: 0.125W; Temperature Coefficient: 100ppm/K; Tolerance: 1%
R17 = RES: RES SMD 1M OHM 5% 1/10W 0603; CLASS: DISCRETE; Manufacturer: Vishay; Manufacturer PN: CRCW06031M00JNEA; PART_NUMBER: CRCW06031M00JNEA; Package Size: 0603; Rated Power: 0.1W; Temperature Coefficient: 200ppm/K; Tolerance: 5%
R18 = RES: CLASS: DISCRETE; Manufacturer: Vishay; Manufacturer PN: CRCW0603243KFKEA; PART_NUMBER: CRCW0603243KFKEA; Package Size: 0603; Rated Power: 0.1W; Temperature Coefficient: 100ppm/K; Tolerance: 1%
R22 = RES: RES 150 OHM 1/10W 1% 0603 SMD; CLASS: DISCRETE; Manufacturer: Panasonic - ECG; Manufacturer PN: ERJ-3EKF1500V; PART_NUMBER: ERJ-3EKF1500V; Package Size: 0603 (1608 Metric); Rated Power: 0.1W, 1/10W; Temperature Coefficient: ±100ppm/°C; Tolerance: ±1%
ST1 = SCREW-TERMINAL: #4 SCREW TERMINAL, PANHEAD; CLASS: DISCRETE; PART_NUMBER: MNT4_PANHEAD
TP1 = TESTPOINT: TEST POINT PC MINI .040"D RED; CLASS: DISCRETE; Manufacturer: Keystone Electronics; Manufacturer PN: 5000; PART_NUMBER: 5000; Package Size: 2.50 Dia
TP2 = TESTPOINT: TEST POINT PC MINI .040"D BLACK; CLASS: DISCRETE; Manufacturer: Keystone Electronics; Manufacturer PN: 5001; PART_NUMBER: 5001; Package Size: 2.50 Dia
TP3 = TESTPOINT: TEST POINT PC MINI .040"D YELLOW; CLASS: DISCRETE; Manufacturer: Keystone Electronics; Manufacturer PN: 5004; PART_NUMBER: 5004; Package Size: 2.50 Dia
TP4 = TESTPOINT: TEST POINT PC MINI .040"D ORANGE; CLASS: DISCRETE; Manufacturer: Keystone Electronics; Manufacturer PN: 5003; PART_NUMBER: 5003; Package Size: 2.50 Dia
U3 U7 = LT8610A: IC REG BUCK SYNC ADJ 3.5A 16MSOP; CLASS: IC; Manufacturer: Linear Technology; Package Size: 16-TFSOP (0.118", 3.00mm Width) Exposed Pad
U4 = ADM7171: IC REG LDO 3.3V 1A 8-LFCSP; CLASS: IC; Manufacturer: Analog Devices Inc; Package Size: 8-WFDFN Exposed Pad, CSP
U5 = 74xxx1G74DC-DLatch: IC POS-EDGE-TRIG D F-F-8-US8; CLASS: IC; Manufacturer: Texas Instruments; Package Size: 8-VFSOP (0.091", 2.30mm Width); Supply Voltage: 0.8 V ~ 3.6 V
U6 = LTC6906_S6: IC OSC SILICON PROG TSOT23-6; CLASS: IC; Manufacturer: Linear Technology; Package Size: SOT-23-6 Thin, TSOT-23-6; Supply Voltage: 2.25 V - 3.6 V
D3-D10 = DIODE_TVS_BI_DIR: TVS DIODE 5V 20V SLP1006P2T; CLASS: DISCRETE; Manufacturer: Semtech Corporation; PART_NUMBER: TMP-2271; Package Size: 0402 (1006 Metric)
J2 J4 J9 = CON4: CONN HDR 2MM R/A W/LATCH 4POS; CLASS: IO; Manufacturer: Harwin Inc
J3 J5 J10 J14-J16 = CON6: CONN HDR 2MM R/A W/LATCH 6POS; CLASS: IO; Manufacturer: Harwin Inc
R24 = RES: CLASS: DISCRETE; Manufacturer: Vishay; Manufacturer PN: CRCW0805100RFKEA; PART_NUMBER: CRCW0805100RFKEA; Package Size: 0805; Rated Power: 0.125W; Temperature Coefficient: 100ppm/K; Tolerance: 1%
R94 R95 = RES: CLASS: DISCRETE; Manufacturer: Vishay; Manufacturer PN: CRCW120660R4FKEA; PART_NUMBER: CRCW120660R4FKEA; Package Size: 1206; Rated Power: 0.25W; Temperature Coefficient: 100ppm/K; Tolerance: 1%
R96 = RES: RES 0.0 OHM 1/10W 0603 SMD; CLASS: DISCRETE; Manufacturer: Vishay/Dale; Manufacturer PN: CRCW06030000Z0EA; PART_NUMBER: CRCW06030000Z0EA; Package Size: 0603 (1608 Metric); Rated Power: 0.1W, 1/10W; Tolerance: Jumper
R97-R100 = RES: TO BE DETERMINED, HEIGHT 0.5mm; CLASS: DISCRETE; PART_NUMBER: TBD_R0603; Package Size: 0603
U9 = MAX3233E: IC TXRX RS232 DUAL250KBPS 20SOIC; CLASS: IC; Manufacturer: Maxim Integrated Products; PART_NUMBER: MAX3233EEWP_G36; Package Size: 20-SOIC (0.295", 7.50mm Width); Supply Voltage: 3 V ~ 3.6 V
U10 = MAX3471xUA: IC TXRX DIFF RS485/422 8-UMAX; CLASS: IC; Manufacturer: Maxim Integrated Products; Package Size: 8-TSSOP, 8-MSOP (0.118", 3.00mm Width); Supply Voltage: 2.5 V ~ 5.5 V
U27 = LTM2889
C43 C51 C60 C69 = CAP: CAP CER 680PF 100V 5% NP0 0805; CLASS: DISCRETE; Dielectric Type: Capacitors; Manufacturer: Kemet; Manufacturer PN: C0805C681J1GACTU; PART_NUMBER: C0805C681J1GACTU; Package Size: 0805 (2012 Metric); Rated Voltage: 100V; Temperature Coefficient: C0G, NP0; Tolerance: ±5%
C44 C52 C61 C70 = CAP: CAP CER 560PF 50V 10% X7R 0603; CLASS: DISCRETE; Dielectric Type: Capacitors; Manufacturer: Murata Electronics North America; Manufacturer PN: GRM188R71H561KA01D; PART_NUMBER: GRM188R71H561KA01D; Package Size: 0603 (1608 Metric); Rated Voltage: 50V; Temperature Coefficient: X7R; Tolerance: ±10%
C45 C46 C54 C55 C63 C64 C72 C73 = CAP: CAP CER 6800PF 50V 10% X7R 0805; CLASS: DISCRETE; Dielectric Type: Capacitors; Manufacturer: Yageo; Manufacturer PN: CC0805KRX7R9BB682; PART_NUMBER: CC0805KRX7R9BB682; Package Size: 0805 (2012 Metric); Rated Voltage: 50V; Temperature Coefficient: X7R; Tolerance: 10%
J6 J12 = CON8: CONN HDR 2MM R/A W/LATCH 8POS; CLASS: IO; Manufacturer: Harwin Inc
R26 R32 R39 R46 = RES: CLASS: DISCRETE; Manufacturer: Vishay; Manufacturer PN: CRCW08055K62FKEA; PART_NUMBER: CRCW08055K62FKEA; Package Size: 0805; Rated Power: 0.125W; Temperature Coefficient: 100ppm/K; Tolerance: 1%
R27 R33 R40 R47 = RES: CLASS: DISCRETE; Manufacturer: Vishay; Manufacturer PN: CRCW0805160KJNEA; PART_NUMBER: CRCW0805160KJNEA; Package Size: 0805; Rated Power: 0.125W; Temperature Coefficient: 200ppm/K; Tolerance: 5%
R28 R29 R34 R35 R41 R42 R48 R49 = RES: CLASS: DISCRETE; Manufacturer: Vishay; Manufacturer PN: CRCW080533K2FKEA; PART_NUMBER: CRCW080533K2FKEA; Package Size: 0805; Rated Power: 0.125W; Temperature Coefficient: 100ppm/K; Tolerance: 1%
U12 U14 U16 U18 U20 U21 = LTC2055_MS8: IC OPAMP CHOPPER 500KHZ 8MSOP; CLASS: IC; Manufacturer: Linear Technology; Package Size: 8-TSSOP, 8-MSOP (0.118", 3.00mm Width); Supply Voltage: 2.7 V - 11 V, 1.35 V - 5.5 V
DN1 DN2 DN6-DN10 = DIODE_DUAL_ACJ: DIODE SCHOTTKY DUAL 30V SOT323; CLASS: DISCRETE; Manufacturer: ON Semiconductor; Package Size: SC-70, SOT-323; Rated Voltage: 800mV @ 100mA
F1-F6 = FUSEHOLDER_2T_2PIN: FUSEBLOCK W/.125A FUSE SMD FST; CLASS: DISCRETE; Manufacturer: Littelfuse Inc; Package Size: SMD w/Holder
J7 J8 J13 = CON3: CONN HDR 2MM R/A W/LATCH 3POS; CLASS: IO; Manufacturer: Harwin Inc
R51 R54 R72 R77 = RES: RES SMD 10K OHM 1% 1/10W 0603; CLASS: DISCRETE; Manufacturer: Vishay; Manufacturer PN: CRCW060310K0FKEA; PART_NUMBER: CRCW060310K0FKEA; Package Size: 0603; Rated Power: 0.1W; Temperature Coefficient: 100ppm/K; Tolerance: 1%
R52 R55 R57 R60 = RES: CLASS: DISCRETE; Manufacturer: Vishay; Manufacturer PN: CRCW060316K2FKEA; PART_NUMBER: CRCW060316K2FKEA; Package Size: 0603; Rated Power: 0.1W; Temperature Coefficient: 100ppm/K; Tolerance: 1%
R53 R56 = RES: CLASS: DISCRETE; Manufacturer: Vishay; Manufacturer PN: CRCW06034K53FKEA; PART_NUMBER: CRCW06034K53FKEA; Package Size: 0603; Rated Power: 0.1W; Temperature Coefficient: 100ppm/K; Tolerance: 1%
R58 R62 = RES: RES 150 OHM 1W 1% 2512 SMD; CLASS: DISCRETE; Manufacturer: Rohm Semiconductor; Manufacturer PN: MCR100JZHF1500; PART_NUMBER: MCR100JZHF1500; Package Size: 2512 (6432 Metric); Rated Power: 1W; Temperature Coefficient: ±100ppm/°C; Tolerance: ±1%
C82 C84 C85 = CAP: CAP CER 0.47UF 16V X7R 0603; CLASS: DISCRETE; Dielectric Type: Ceramic; Manufacturer: Kemet; Manufacturer PN: C0603C474K4RAC; PART_NUMBER: C0603C474K4RAC; Package Size: 0603; Rated Voltage: 16V; Temperature Coefficient: X7R; Tolerance: 10%
C83 C86 = CAP: CAP CER 4.7UF 6.3V 10% X7R 0805; CLASS: DISCRETE; Dielectric Type: Capacitors; Manufacturer: Kemet; Manufacturer PN: C0805C475K9RACTU; PART_NUMBER: C0805C475K9RACTU; Package Size: 0805 (2012 Metric); Rated Voltage: 6.3V; Temperature Coefficient: X7R; Tolerance: 10%
J11 = CON12: CONN HDR 2MM R/A W/LATCH 12POS; CLASS: IO; Manufacturer: Harwin Inc
JP2 = JUMPER_SELECT-QUAD: QUAD SELECT JUMPER; CLASS: IO
Q1-Q5 = MOSFET_I_EN_GSD: MOSFET N-CH 60V 2A SOT23-3; CLASS: DISCRETE; Manufacturer: Vishay/Siliconix; Package Size: SOT-23-3, TO-236-3, Micro3™, SSD3, SST3; Rated Power: 1.25W
R73 R78 = RES: RES .05 OHM 1/2W 1% 1206 SMD; CLASS: DISCRETE; Manufacturer: Stackpole Electronics Inc; Manufacturer PN: CSR1206FK50L0; PART_NUMBER: CSR1206FK50L0; Package Size: 1206 (3216 Metric); Rated Power: 0.5W, 1/2W; Temperature Coefficient: ±100ppm/°C; Tolerance: ±1%
R74 R80 = RES: CLASS: DISCRETE; Manufacturer: Vishay; Manufacturer PN: CRCW06032K00FKEA; PART_NUMBER: CRCW06032K00FKEA; Package Size: 0603; Rated Power: 0.1W; Temperature Coefficient: 100ppm/K; Tolerance: 1%
R75 R76 R79 = RES: RES SMD 330 OHM 5% 1/10W 0603; CLASS: DISCRETE; Manufacturer: Vishay; Manufacturer PN: CRCW0603330RJNEA; PART_NUMBER: CRCW0603330RJNEA; Package Size: 0603; Rated Power: 0.1W; Temperature Coefficient: 200ppm/K; Tolerance: 5%
R101-R103 = RES: CLASS: DISCRETE; Manufacturer: Vishay; Manufacturer PN: CRCW0603165KFKEA; PART_NUMBER: CRCW0603165KFKEA; Package Size: 0603; Rated Power: 0.1W; Temperature Coefficient: 100ppm/K; Tolerance: 1%
R107-R109 = RES: TO BE DETERMINED, HEIGHT 0.6mm; CLASS: DISCRETE; PART_NUMBER: TBD_R1206; Package Size: 1206
R111-R113 = RES: RES SMD 100 OHM 1% 1/10W 0603; CLASS: DISCRETE; Manufacturer: Vishay; Manufacturer PN: CRCW0603100RFKEA; PART_NUMBER: CRCW0603100RFKEA; Package Size: 0603; Rated Power: 0.1W; Temperature Coefficient: 100ppm/K; Tolerance: 1%
U22 U23 = LT1910: IC MOSFET DRIVER HIGH-SIDE 8SOIC; CLASS: DISCRETE; Manufacturer: Linear Technology; Package Size: 8-SOIC (0.154", 3.90mm Width)
U25 = AM26LS32A

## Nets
3.3V: C8.1 C9.1 C10.1 C11.1 C12.1 C13.1 C14.1 C15.1 C24.1 C39.1 C40.1 C41.1 C47.1 C56.1 C65.1 C74.1 C80.1 C81.1 C88.1 C90.1 D1.A DN1.2(C) DN2.2(C) DN9.2(C) DN10.2(C) J3.2 J6.8 JP2.5 R1.1 R3.1 R5.1 R7.1 R72.1 R77.1 R91.1 R92.1 R93.1 SB3.2 TP3.1(TP) U1.2(VDD) U1.16(VDD) U1.30(AVDD) U1.37(VDD) U1.46(VDD) U1.62(VDD) U1.86(VDD) U2.3(EN) U4.1(VOUT1) U4.2(VOUT2) U9.9(Vcc) U9.10(\\~{FORCEOFF}) U10.8(Vcc) U12.8(V+) U14.8(V+) U16.8(V+) U18.8(V+) U20.8(V+) U21.8(V+) U26.4(VCC) U27.PVCC U27.VCC U27.VL
5V: C29.2 C34.1 C35.1 C36.1 C87.1 D2.A DN6.2(C) DN7.2(C) DN8.2(C) F5.2 JP2.4 L2.2 R17.2 R20.1 SB4.2 SB6.1 TP4.1(TP) U7.14(BIAS) U25.16(VCC)
15V: C20.1 C33.1 F1.2 F2.2 F3.2 J1.1 J6.6 JP2.3 JR1.1 JR3.1 R13.1 R21.1 R88.1 R90.1 TP1.1(TP) U3.5(VIN1) U3.6(VIN2) U7.5(VIN1) U7.6(VIN2)
GND_EARTH: C91.1 ST1.1
GND_SIGNAL: C1.2 C2.2 C3.2 C4.2 C5.2 C6.2 C7.2 C8.2 C9.2 C10.2 C11.2 C12.2 C13.2 C14.2 C15.2 C17.2 C19.2 C20.2 C21.2 C22.2 C23.2 C24.2 C25.2 C26.2 C27.2 C28.2 C30.2 C32.2 C33.2 C34.2 C35.2 C36.2 C37.2 C39.2 C40.2 C41.2 C43.2 C44.2 C47.2 C51.2 C52.2 C56.2 C60.2 C61.2 C65.2 C69.2 C70.2 C74.2 C76.2 C77.2 C78.2 C79.2 C80.2 C81.2 C82.2 C83.2 C84.2 C85.2 C86.2 C87.2 C88.2 C89.2 C90.2 C91.2 D3.1(A1) D4.1(A1) D5.1(A1) D6.1(A1) D7.1(A1) D8.1(A1) D9.1(A1) D10.1(A1) DN1.1(A) DN2.1(A) DN6.1(A) DN7.1(A) DN8.1(A) DN9.1(A) DN10.1(A) J1.2 J3.3 J4.4 J5.5 J6.5 J6.7 J7.3 J8.3 J9.4 J11.2 J12.8 J13.2 J15.5 J16.5 JR1.3 JR2.3 JR3.3 Q3.2(S) Q4.2(S) Q5.2(S) R9.2 R10.2 R11.2 R14.2 R15.2 R16.2 R18.2 R19.2 R22.2 R23.2 R53.1 R56.1 R59.2 R61.2 R89.2 R101.2 R102.2 R103.2 SB5.1 SW1.1 SW1.2 TP2.1(TP) U1.15(VSS) U1.28(VREF-/RA9) U1.31(AVSS) U1.36(VSS) U1.45(VSS) U1.65(VSS) U1.75(VSS) U2.2(GND) U3.8(GND) U3.17(GNDPAD) U4.6(GND) U4.9(GND) U5.4(Gnd) U6.2(GND) U7.8(GND) U7.17(GNDPAD) U9.5(FORCEON) U9.18(Gnd) U10.5(GND) U12.4(V-) U14.4(V-) U16.4(V-) U18.4(V-) U20.4(V-) U21.4(V-) U22.1(GND) U23.1(GND) U25.8(GND) U26.2(VSS) U27.\\R\E(\\~{R}E) U27.GND
AN0_LOADCELL: U1.25(PGED3/AN0/CN2/RB0) U21.1(OutA) U21.2(INA-)
AN1_POSITION: U1.24(PGEC3/AN1/CN3/RB1) U21.6(INB-) U21.7(OutB)
AN10_DIFFPB: U1.34(AN10/RB10) U20.6(INB-) U20.7(OutB)
AN11_TORQ_DIFFPA: U1.35(AN11/RB11) U20.1(OutA) U20.2(INA-)
AN16_VSENSE: C46.2 U1.6(AN16/T2CK/T7CK/RC1) U12.6(INB-) U12.7(OutB)
AN17_IBUS: C55.2 U1.7(AN17/T3CK/T6CK/RC2) U14.6(INB-) U14.7(OutB)
AN18_ILOAD: C64.2 U1.8(AN18/T4CK/T9CK/RC3) U16.6(INB-) U16.7(OutB)
AN19_IBOOST: C73.2 U1.9(AN19/T5CK/T8CK/RC4) U18.6(INB-) U18.7(OutB)
ASIG_IBOOST_3V: J6.4 R46.1
ASIG_IBUS_3V: J6.2 R32.1
ASIG_ILOAD_3V: J6.3 R39.1
ASIG_VBUS_3V: J6.1 R26.1
CAN1_RX: U1.87(C1RX/RF0) U27.RXD
CAN1_TX: U1.88(C1TX/RF1) U27.TXD
CANGND: J2.3 R96.2 R97.1 R98.2 U27.GND2
CANH: J2.1 R94.1 U27.CANH
CANL: J2.2 R95.2 U27.CANL
D1+: J14.1 R114.2
D1-: J14.4 R117.1
D2+: J14.2 R115.2
D2-: J14.5 R118.1
D3+: J14.3 R116.2
D3-: J14.6 R119.1
EEPROM_WP: R93.2 U1.58(SCL2/RA2) U26.5(WP)
ENC_A_A: J11.3 R107.1 U25.2(1A)
ENC_A_B: J11.4 R107.2 U25.1(1B)
ENC_B_A: J11.5 R108.1 U25.6(2A)
ENC_B_B: J11.6 R108.2 U25.7(2B)
ENC_Z_A: J11.7 R109.1 U25.10(3A)
ENC_Z_B: J11.8 R109.2 U25.9(3B)
HALL_U: J11.11 R79.1
HALL_V: J11.10 R76.1
HALL_W: J11.9 R75.1
I2C1_SCL: R91.2 U1.57(SCL1/RG2) U26.1(SCL)
I2C1_SDA: R92.2 U1.56(SDA1/RG3) U26.3(SDA)
LASERRNGPWR_15V_INPUT: J10.6 R73.1 R88.2 U22.8(V+)
LASERRNGPWR_15V_SWITCHED: F4.2 Q1.2(S)
MCLR: R4.2 R24.1 U1.13(~{MCLR})
OSC1: C6.1 R5.2 R6.2 U1.63(OSC1/CLKIN/RC12) Y2.1
OSC2: C7.1 R6.1 U1.64(OSC2/CLKO/RC15) Y2.2
PhaseA: JR1.2 U3.1(SYNC) U5.2(D) U5.3(~{Q})
PhaseB: JR3.2 U5.5(Q) U7.1(SYNC)
PSIGA_10V: J7.2 R51.1
PSIGB_10V: J8.2 R54.1
PWM1H: J12.1 U1.94(PWM1H/RE1)
PWM1L: J12.2 U1.93(PWM1L/RE0)
PWM2H: J12.3 U1.99(PWM2H/RE3)
PWM2L: J12.4 U1.98(PWM2L/RE2)
PWM3H: J12.5 U1.3(PWM3H/RE5)
PWM3L: J12.6 U1.100(PWM3L/RE4)
PWM4L: J12.7 U1.4(PWM4L/RE6)
RB3_ENC_Z: U1.22(AN3/INDX/CN5/RB3) U25.11(3Y)
RB4_ENC_A: U1.21(AN4/QEA/CN6/RB4) U25.3(1Y)
RB5_ENC_B: U1.20(AN5/QEB/CN7/RB5) U25.5(2Y)
RB6_PGEC1: J3.5 U1.26(PGEC1/AN6/OCFA/RB6)
RB7_PGED1: J3.4 U1.27(PGED1/AN7/RB7)
RD1-5VPG: C37.1 R20.2 U1.76(OC2/RD1) U7.15(PG)
RD2_GASBYPASS_EN: R112.2 U1.77(OC3/RD2)
RD3_STEPPER_ENABLE: R111.2 U1.78(OC4/RD3)
RD4_HALL_W: C82.1 DN6.3(J) R75.2 U1.81(OC5/CN13/RD4)
RD5_HALL_V: C84.1 DN7.3(J) R76.2 U1.82(OC6/CN14/RD5)
RD6_HALL_U: C85.1 DN8.3(J) R79.2 U1.83(OC7/CN15/RD6)
RD7_AUX: R113.2 U1.84(OC8/UPDN/CN16/RD7)
RD12_LRF_EN: R74.1 U1.79(IC5/RD12) U22.4(IN)
RD13_NFAULT_LRFPOW: R72.2 U1.80(IC6/CN19/RD13) U22.3(~{FAULT})
RF12: U1.40(~{U2CTS}/RF12) U10.2(~{RE})
RF13: U1.39(~{U2RTS}/RF13) U10.3(DE)
RG0_CAN1_SILENT: U1.90(C2RX/RG0) U27.S
RG1_CAN1_ENABLE: U1.89(C2TX/RG1) U27.ON
RG14_SW1_NFLT: R77.2 U1.95(RG14) U23.3(~{FAULT})
RG15_SW1_EN: R80.1 U1.1(RG15) U23.4(IN)
RS232_CTS: J5.4 U9.20(R2IN)
RS232_RTS: J5.2 U9.19(T2OUT)
RS232_RXD: J5.3 U9.8(R1IN)
RS232_TXD: J5.1 U9.7(T1OUT)
RS485_A: J4.2 SB2.1 U10.6(A)
RS485_B: J4.1 SB1.1 U10.7(B)
SOSCI: C5.1 U1.73(PGED2/SOSCI/CN1/RC13) Y1.2
SOSCO: C4.1 U1.74(PGEC2/SOSCO/T1CK/CN0/RC14) Y1.1
SPI1_MISO: D9.2(A2) J16.3 U1.54(SDI1/RF7)
SPI1_MOSI: D8.2(A2) J16.2 U1.53(SDO1/RF8)
SPI1_SCLK: D7.2(A2) J16.1 U1.55(SCK1/INT0/RF6)
SPI1_SS: D10.2(A2) J16.4 U1.23(AN2/~{SS1}/CN4/RB2)
SPI2_MISO: D5.2(A2) J15.3 U1.11(SDI2/CN9/RG7)
SPI2_MOSI: D4.2(A2) J15.2 U1.12(SDO2/CN10/RG8)
SPI2_SCLK: D3.2(A2) J15.1 U1.10(SCK2/CN8/RG6)
SPI2_SS: D6.2(A2) J15.4 U1.14(~{SS2}/CN11/RG9)
SW1_INPUT: J13.3 R78.1 R90.2 U23.8(V+)
U1CTS: U1.47(IC7/~{U1CTS}/CN20/RD14) U9.1(R2OUT)
U1RTS: U1.48(IC8/~{U1RTS}/CN21/RD15) U9.3(T2IN)
U1RXD: U1.52(U1RX/RF2) U9.6(R1OUT)
U1TXD: U1.51(U1TX/RF3) U9.4(T1IN)
U2RXD: SB1.2 U1.49(U2RX/CN17/RF4) U10.1(RO)
U2TXD: SB2.2 U1.50(U2TX/CN18/RF5) U10.4(DI)
N08765: C1.1 C2.1 R1.2 R2.2
N08773: R2.1 U1.85(VCAP)
N14987: JP1.1 R3.2 R4.1 SW1.3 SW1.4
N25385: F5.1 J11.1
N38405: C3.1 JP1.2
N39747: U1.29(VREF+/RA10) U2.5(Vref)
N47726: J3.1 R24.2
N72482: C77.1 DN9.3(J) R55.2 U20.5(INB+)
N72600: R51.2 R52.1 R53.2 R99.2
N72690: C76.1 DN10.3(J) R52.2 U20.3(INA+)
N72804: R54.2 R55.1 R56.2 R100.2
N72852: F2.1 J8.1 R100.1
N75830: F1.1 J7.1 R99.1
N76571: F3.1 J9.1
N76619: J9.2 R57.2 R58.1
N76675: J9.3 R58.2 R59.1
N76787: C78.1 DN1.3(J) R57.1 U21.3(INA+)
N77226: F4.1 J10.1
N77274: J10.2 R60.2 R62.1
N77330: J10.3 R61.1 R62.2
N77442: C79.1 DN2.3(J) R60.1 U21.5(INB+)
N78880: C45.2 R28.1 U12.1(OutA) U12.2(INA-)
N79426: C45.1 R26.2 R27.1
N79442: C43.1 R27.2 U12.3(INA+)
N79600: C46.1 R28.2 R29.1
N79616: C44.1 R29.2 U12.5(INB+)
N83438: C54.2 R34.1 U14.1(OutA) U14.2(INA-)
N83538: C54.1 R32.2 R33.1
N83554: C51.1 R33.2 U14.3(INA+)
N83666: C55.1 R34.2 R35.1
N83682: C52.1 R35.2 U14.5(INB+)
N84265: C63.2 R41.1 U16.1(OutA) U16.2(INA-)
N84365: C63.1 R39.2 R40.1
N84381: C60.1 R40.2 U16.3(INA+)
N84493: C64.1 R41.2 R42.1
N84509: C61.1 R42.2 U16.5(INB+)
N85113: C72.2 R48.1 U18.1(OutA) U18.2(INA-)
N85213: C72.1 R46.2 R47.1
N85229: C69.1 R47.2 U18.3(INA+)
N85341: C73.1 R48.2 R49.1
N85357: C70.1 R49.2 U18.5(INB+)
N98820: Q1.1(G) U22.5(GATE)
N98894: Q1.3(D) R73.2 U22.6(SENSE)
N99153: C83.1 R74.2 U22.2(TIMER)
N109964: C17.1 C27.1 C28.1 JR2.1 U3.13(INTVCC) U5.6(~{Clr}) U5.7(~{Pre}) U5.8(Vcc) U6.6(V+)
N110102: C16.1 R8.1 R9.1 U3.16(FB)
N110130: C16.2 C21.1 C22.1 C23.1 L1.2 R8.2 R12.1 U3.14(BIAS) U4.7(VIN1) U4.8(VIN2)
N110228: R7.2 R10.1 U4.3(SNS)
N110370: C18.2 L1.1 U3.9(SW1) U3.10(SW2) U3.11(SW3)
N110394: C18.1 U3.12(BST)
N110516: R11.1 U3.3(RT)
N110530: C19.1 U3.2(TR/SS)
N110898: C26.1 U4.4(SS)
N110954: C25.1 R12.2 U3.15(PG) U4.5(EN)
N111056: R13.2 R15.1 U3.4(EN/UV)
N111200: U5.1(Clk) U6.1(OUT1)
N111222: R16.1 U6.4(SET)
N111288: JR2.2 U6.3(DIV)
N113208: R21.2 R23.1 U7.4(EN/UV)
N113286: D2.C R22.1
N113430: C29.1 R17.1 R18.1 U7.16(FB)
N113814: C31.2 L2.1 U7.9(SW1) U7.10(SW2) U7.11(SW3)
N113838: C31.1 U7.12(BST)
N113850: C30.1 U7.13(INTVCC)
N113978: R19.1 U7.3(RT)
N113992: C32.1 U7.2(TR/SS)
N133871: D1.C R14.1
N140572: F6.2 Q2.2(S)
N140988: Q2.1(G) U23.5(GATE)
N141012: Q2.3(D) R78.2 U23.6(SENSE)
N141056: C86.1 R80.2 U23.2(TIMER)
N168303: C89.1 SB3.1 SB4.1 U2.4(Vin)
N249678: J10.4 J10.5 R89.1
N306497: F6.1 J13.1
N326336: R94.2 R95.1 U27.SPLIT+
N326647: R96.1 U27.RS
N327074: R98.1 U27.VCC2
N327081: R97.2 U27.ADJ
N348444: Q4.1(G) R102.1 R112.1
N352220: Q3.1(G) R101.1 R111.1
N352274: Q5.1(G) R103.1 R113.1
N352849: Q3.3(D) R117.2
N352881: Q4.3(D) R118.2
N352913: Q5.3(D) R119.2
N363907: SB6.2 U25.4(G)
N363963: SB5.2 U25.12(\\G)
N375304: JP2.1 R114.1 R115.1 R116.1

Not connected (* = marked no-connect by the designer): J2 4*; J3 6*; J4 3*; J5 6*; J11 12*; J15 6*; J16 6*; JP2 2*; U1 5(PWM4H/RE7)* 17(TMS/RA0)* 18(AN20/~{FLTA}/INT1/RE8)* 19(AN21/~{FLTB}/INT2/RE9)* 32(AN8/RB8)* 33(AN9/RB9)* 38(TCK/RA1)* 41(AN12/RB12)* 42(AN13/RB13)* 43(AN14/RB14)* 44(AN15/OCFB/CN12/RB15)* 59(SDA2/RA3)* 60(TDI/RA4)* 61(TDO/RA5)* 66(INT3/RA14)* 67(INT4/RA15)* 68(IC1/RD8)* 69(IC2/RD9)* 70(IC3/RD10)* 71(IC4/RD11)* 72(OC1/RD0)* 91(AN22/CN22/RA6)* 92(AN23/CN23/RA7)* 96(RG12)* 97(RG13)*; U2 1(Vbias)*; U3 7(NC)*; U6 5(GRD); U7 7(NC)*; U9 2(\~{INVALI}D)* 11(V+_1)* 12(V+_2)* 13(C1+)* 14(C1-)* 15(C2+)* 16(C2-)* 17(V-)*; U22 7(NC)*; U23 7(NC)*; U25 13(4Y)* 14(4A)* 15(4B)*

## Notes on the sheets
sheet 1
- DNI
- COMPONENTS IN THIS NETWORK
  TO BE PLACED WITHIN 0.25" OF
  MCLR PIN
- RESET BUTTON
- REMOVE JUMPER
  FOR PROGRAMMING
- SECONDARY OSC
- ATTEMPT GUARD TRACES
  SEE DSPIC REFERENCE MANUAL
- DNI
- PRECISION VOLTAGE REFERENCE:
  FOR 3.3V REF, USE REF1933 AND BRIDGE TO 5V
  FOR 3.0V REF, USE REF1930 AND BRIDGE TO 3V3
- PRIMARY OSC
- PLACE 0.1uF NEAR
  NUMBERED TERMINALS
  SAME SIDE AS IC
- 2
- 16
- 30
- 37
- 46
- 62
- 86
- 29
- 15
- 31
- 38
- 45
- 65
- 75
- 29
sheet 2
- 3.3V STEPDOWN
- CCM
- DNI
- Vfb = 0.97V
- Burst
- INPUT POWER
- Primary Step Down Voltage = 3.45V
- Undervoltage and
  Enable at 1.0V (10VIN)
- Power Good Signal holds final until
  nearly charged
- 200kHz
- Caution - INTVcc not really supposed to be used!
- 200kHz
- 400kHz
- Guard Trace wraps around  trace of pin 4
- H = DIV 10
  None = DIV 3
  L = DIV 1
- JR2 = L
- 5V STEPDOWN
- CCM
- DNI
- Burst
- Primary Step Down Voltage = 5.00V
- Vfb = 0.97V
- Final System voltage = 5.0V
- Undervoltage and
  Enable at 1.0V (10VIN)
- Power Good Signal holds final until
  nearly charged
- EMI SUPPRESSION
- WIRE TO ONE OF 4 MOUNTING SCREWS
sheet 3
- MPLAB ICD CONNECTOR
- BUS VOLTAGE ADJ:
  DNI FOR 5V
  56.2K & 13.0K FOR 3.3V
- CANBUS
- STEPPER MOTOR RS485
- CAN MODES:
  - NORMAL MODE: ON: HIGH S: LOW
  - SILENT MODE: ON: HIGH S: HIGH
  - OFF MODE: ON: LOW
- SLEW RATE CONTROL: (RS PIN)
  RSL < 4K for high data rates
  Max 200K
- NOTE:
  FOR FLAPPING FOIL CONFIGURATION
  - DNI: U10, C40
  - Connect SB1 & SB2
- RS232
- SPI
- SPI
sheet 4
- GEN HOUSING CONFIG:
  OMEGA DIFF PRESSURE / TORQUE SENSOR
  OUTPUT 0-10VDC SUPPLY 15VDC
  DO NOT DIRECTLY ATTACH TORQUE SENSOR USE REDLION
- GAS SPRING CONFIG:
  HONEYWELL PRESSURE SENSOR A
  0-10VDC 4WIRE 15VDC SUPPLY
- BATTERY HOUSING CONFIG:
  10K  1% PULLUP HERE
- 100Hz LPF
- 100Hz LPF
- APPROXIMATE OUTPUT
  0-3.1 V
  0.8 mV / ADC COUNT @ 12-BIT
- GAS SPRING CONFIG:
  HONEYWELL PRESSURE SENSOR B
  0-10VDC 4WIRE 15VDC SUPPLY
- BATTERY HOUSING CONFIG:
  10K  1% PULLUP HERE
- 100Hz LPF
- 100Hz LPF
- APPROXIMATE OUTPUT
  0-3.1 V
  0.8 mV / ADC COUNT @ 12-BIT
- GAS SPRING CONFIG:
  LOAD CELL ICA5
  OUTPUT 4-20mA 2-WIRE
  SUPPLY 7.5-28VDC
  LOOP ON PINS 1 & 2
- APPROXIMATE OUTPUT
  0.64 V  = 0 LBS
  3.20 V  = 10,000 LBS
  3.15 LBS / ADC COUNT @ 12-BIT
  OFFSET = 794 COUNTS
- 100Hz LPF
- FROM LOAD CELL
  4mA  =            0 LBS
  20mA = 10000 LBS
  MAX SHUNT RES 365 OHM @ 15VIN
- GAS SPRING CONFIG:
  LASER RANGE FINDER MRL-ML1
  OUTPUT 0-20mA 4-WIRE
  SUPPLY 15-24VDC
- APPROXIMATE OUTPUT
  0 V  = 0 m
  3.20 V  = 2400 mm
   0.6 mm / ADC COUNT @ 12-BIT
- 100Hz LPF
- DO NOT LOAD
- FROM LASER RANGE FINDER
  (PRECONFIGURED MAX 2.4m)
  0 mA  =    0 m
  20mA = 2.4 m
sheet 5
- MOTOR DIGITAL INPUTS
- MOTOR DIGITAL OUTPUTS
- ACTIVE HIGH: SB G
  ACTIVE LOW: SB \G
- LASER RANGEFINDER POWER SWITCHING
- DNI
- Current Limiting Resistor:
  Rs = 50mV/Iset
  Iset =     1A
- MAX 120kHz
- Approximate self reset
  700ms without resistor.
- MAX 1kHz
- NOTE (FIX POST REANNOTATE):
  FOR FLAPPING FOIL CONFIGURATION
  - DNI: DN3, DN4, DN5, DN6, DN7, DN8,
             C88, C87, C89, C82, C84, C85,
             R65,R68,R71.
  - REPLACE: R63, R64, R66, R67, R69,
             R75, R76, R79 with RES 0 OHM,
             P/N CRCW08050000Z0EA
- DNI
- AUXILARY SWITCHED POWER
- MAX 1kHz
- Current Limiting Resistor:
  Rs = 50mV/Iset
  Iset =     1A
- MAX 1kHz
- Approximate self reset
  700ms without resistor.
- IF TOO LARGE
  CAN USE SM TRI JUMPER
sheet 6
- FILTER CUTOFF 2kHz, -72dB @ 16kHz
- BUS VOLTAGE = 0 to 400V
  VOUT = 0 to 3V pre-filter
- GEN HOUSING CONFIG:
  VOLTAGE/CURRENT SHUNT MONITOR INPUTS
  SINGLE-ENDED 0-3V
- FILTER CUTOFF 2kHz, -72dB @ 16kHz
- FILTER CUTOFF 2kHz, -72dB @ 16kHz
- FILTER CUTOFF 2kHz, -72dB @ 16kHz
